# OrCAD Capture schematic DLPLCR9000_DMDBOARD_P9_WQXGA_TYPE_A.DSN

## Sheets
1 PAGE-01 Title Page
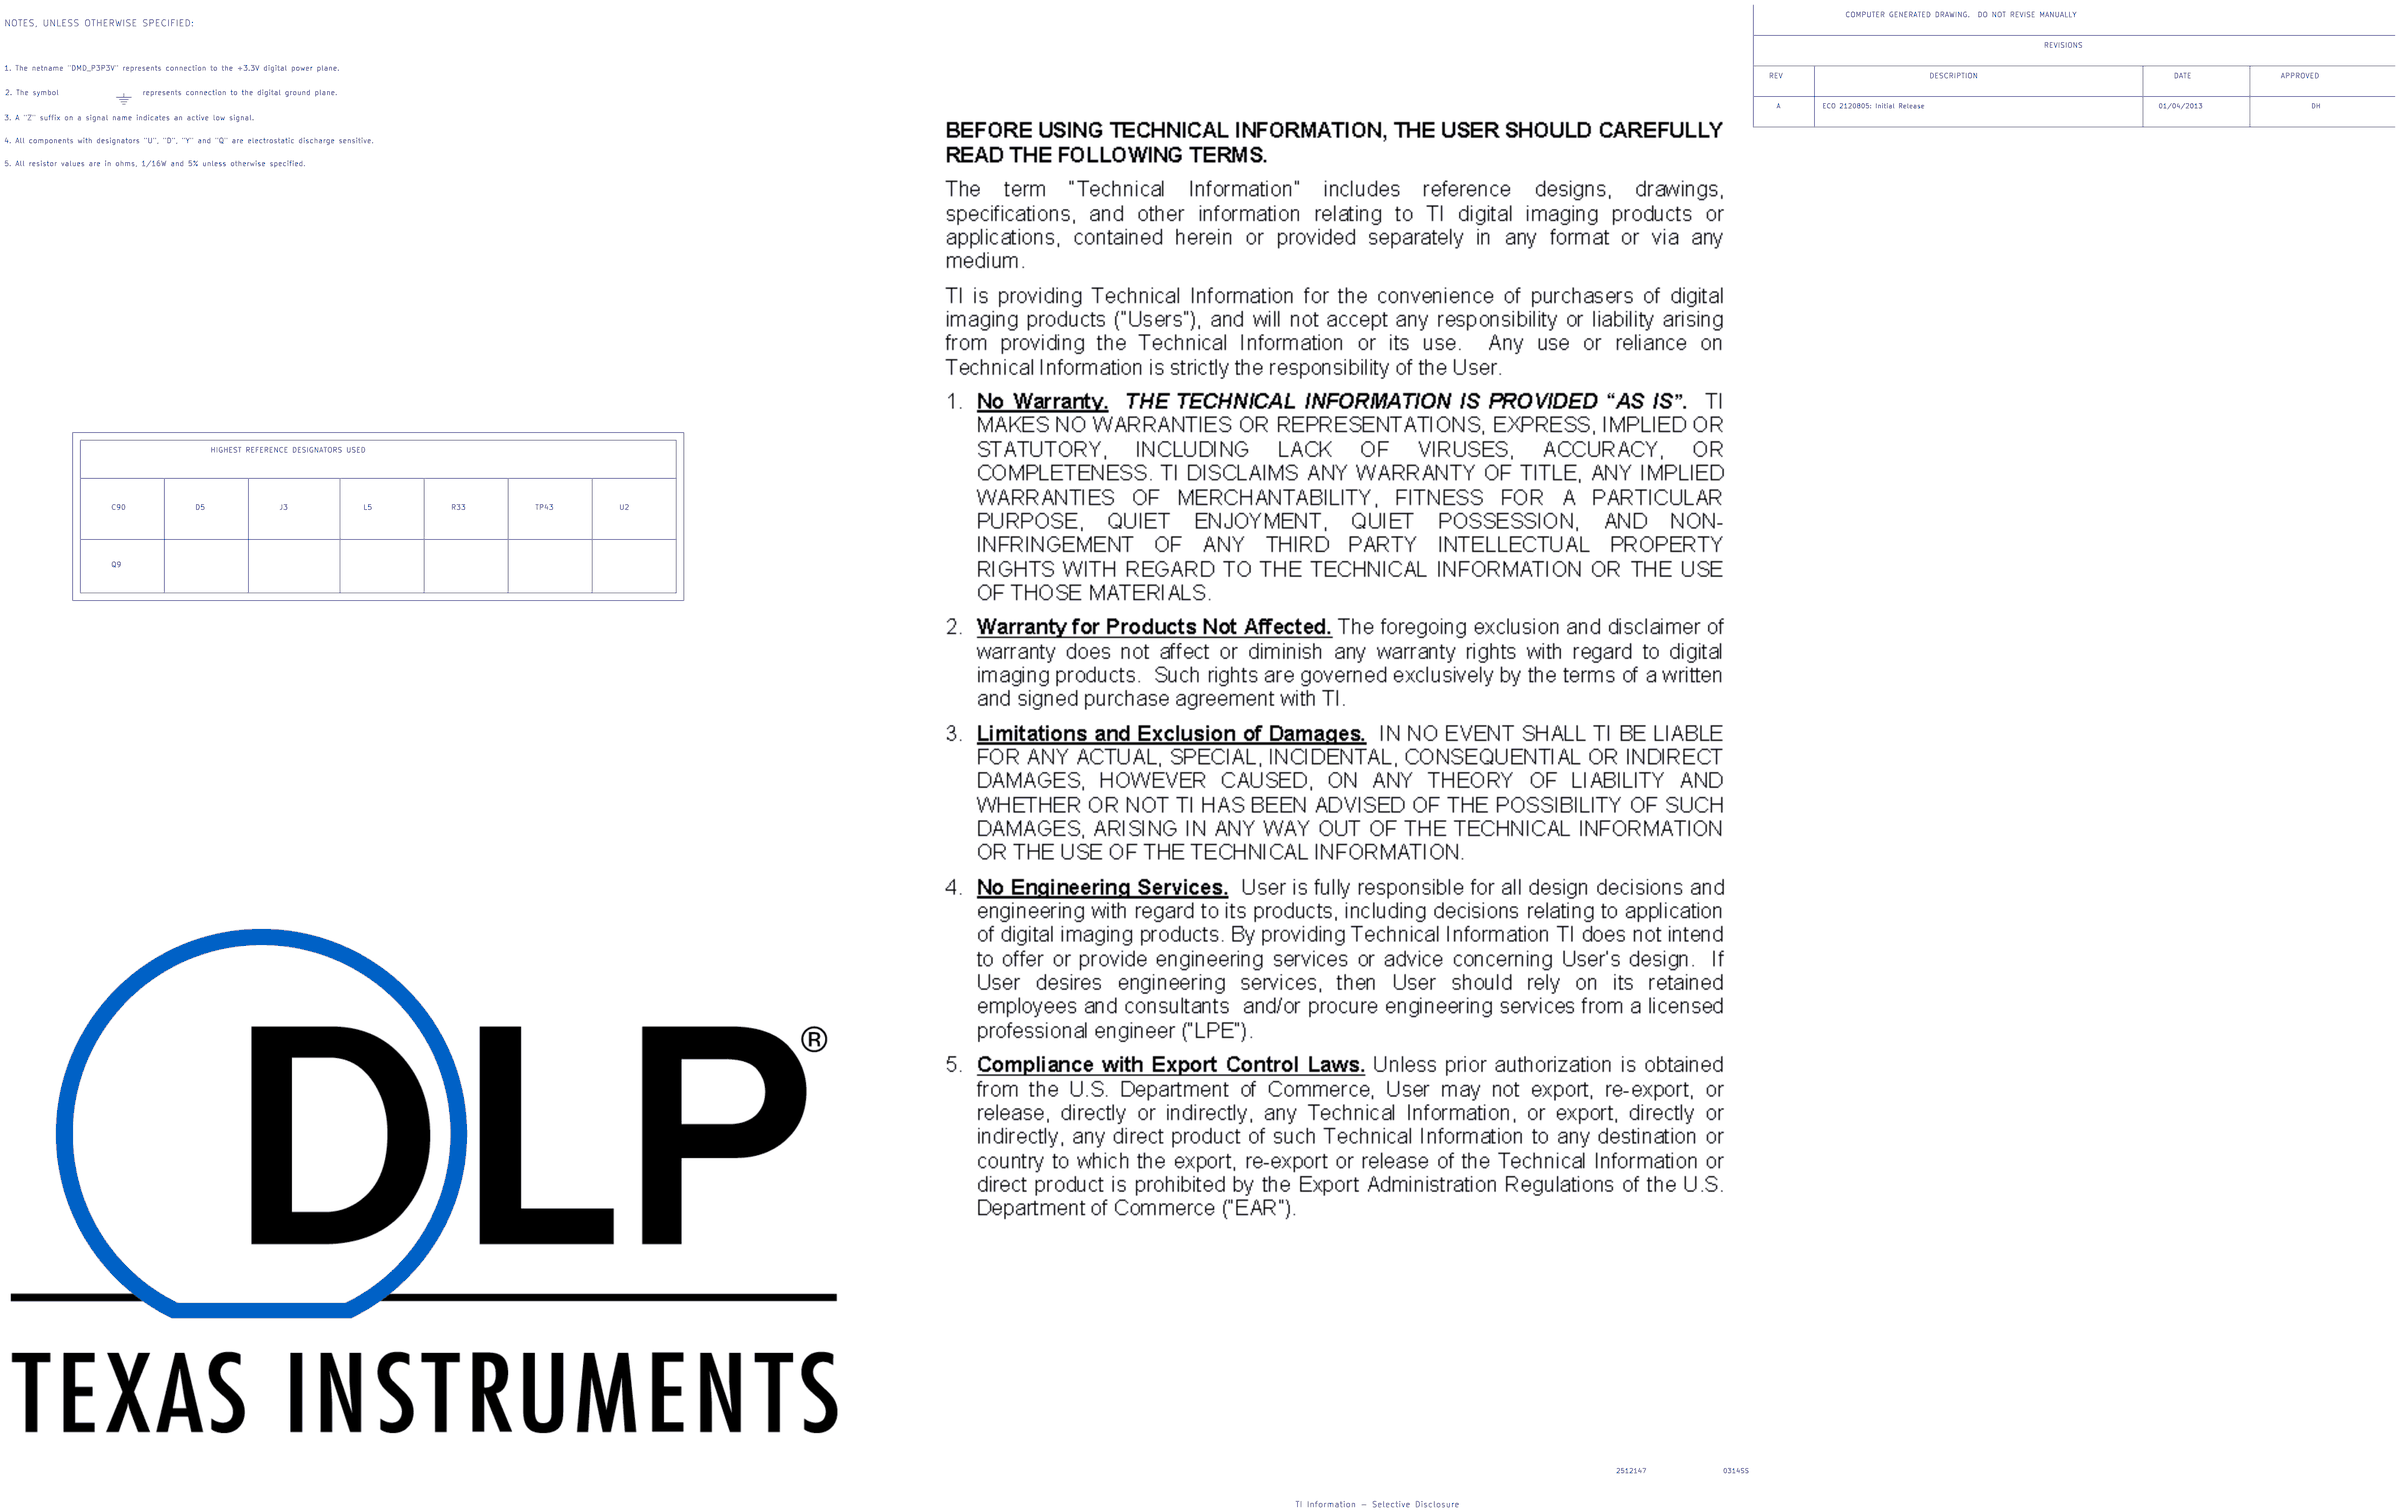
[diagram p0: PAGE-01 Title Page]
2 PAGE-02 Block Diagram
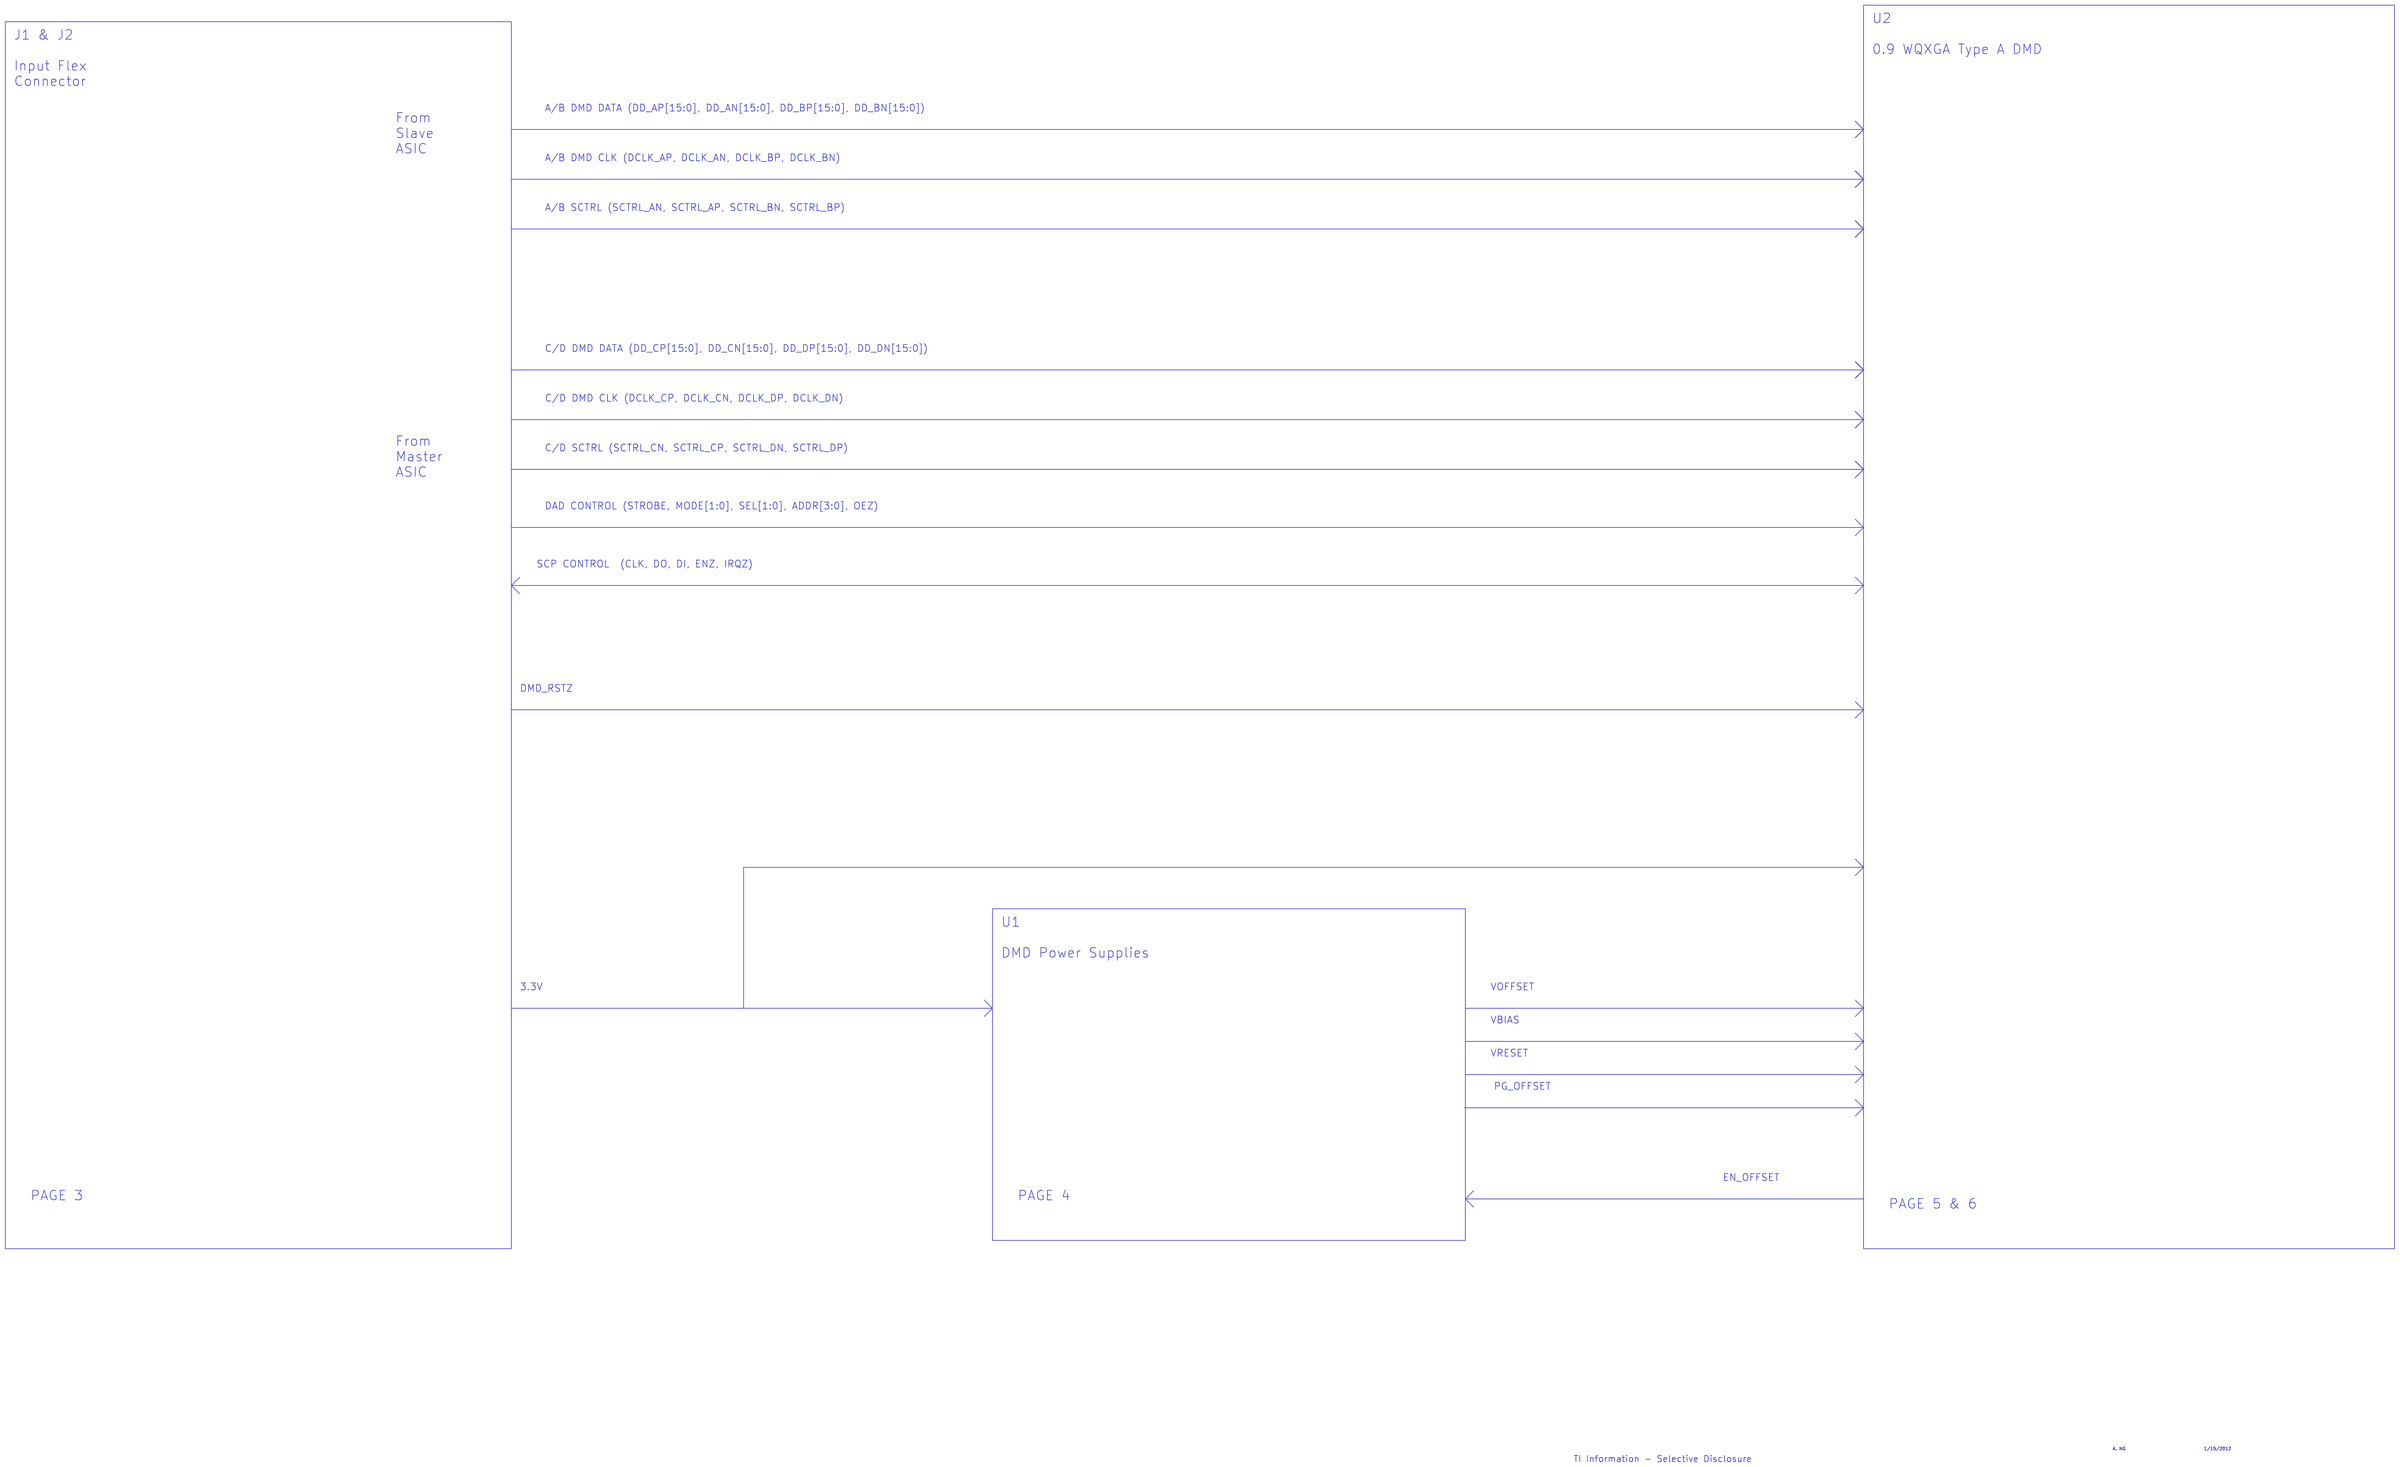
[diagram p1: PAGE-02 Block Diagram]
3 PAGE-03 Input Conn: size D
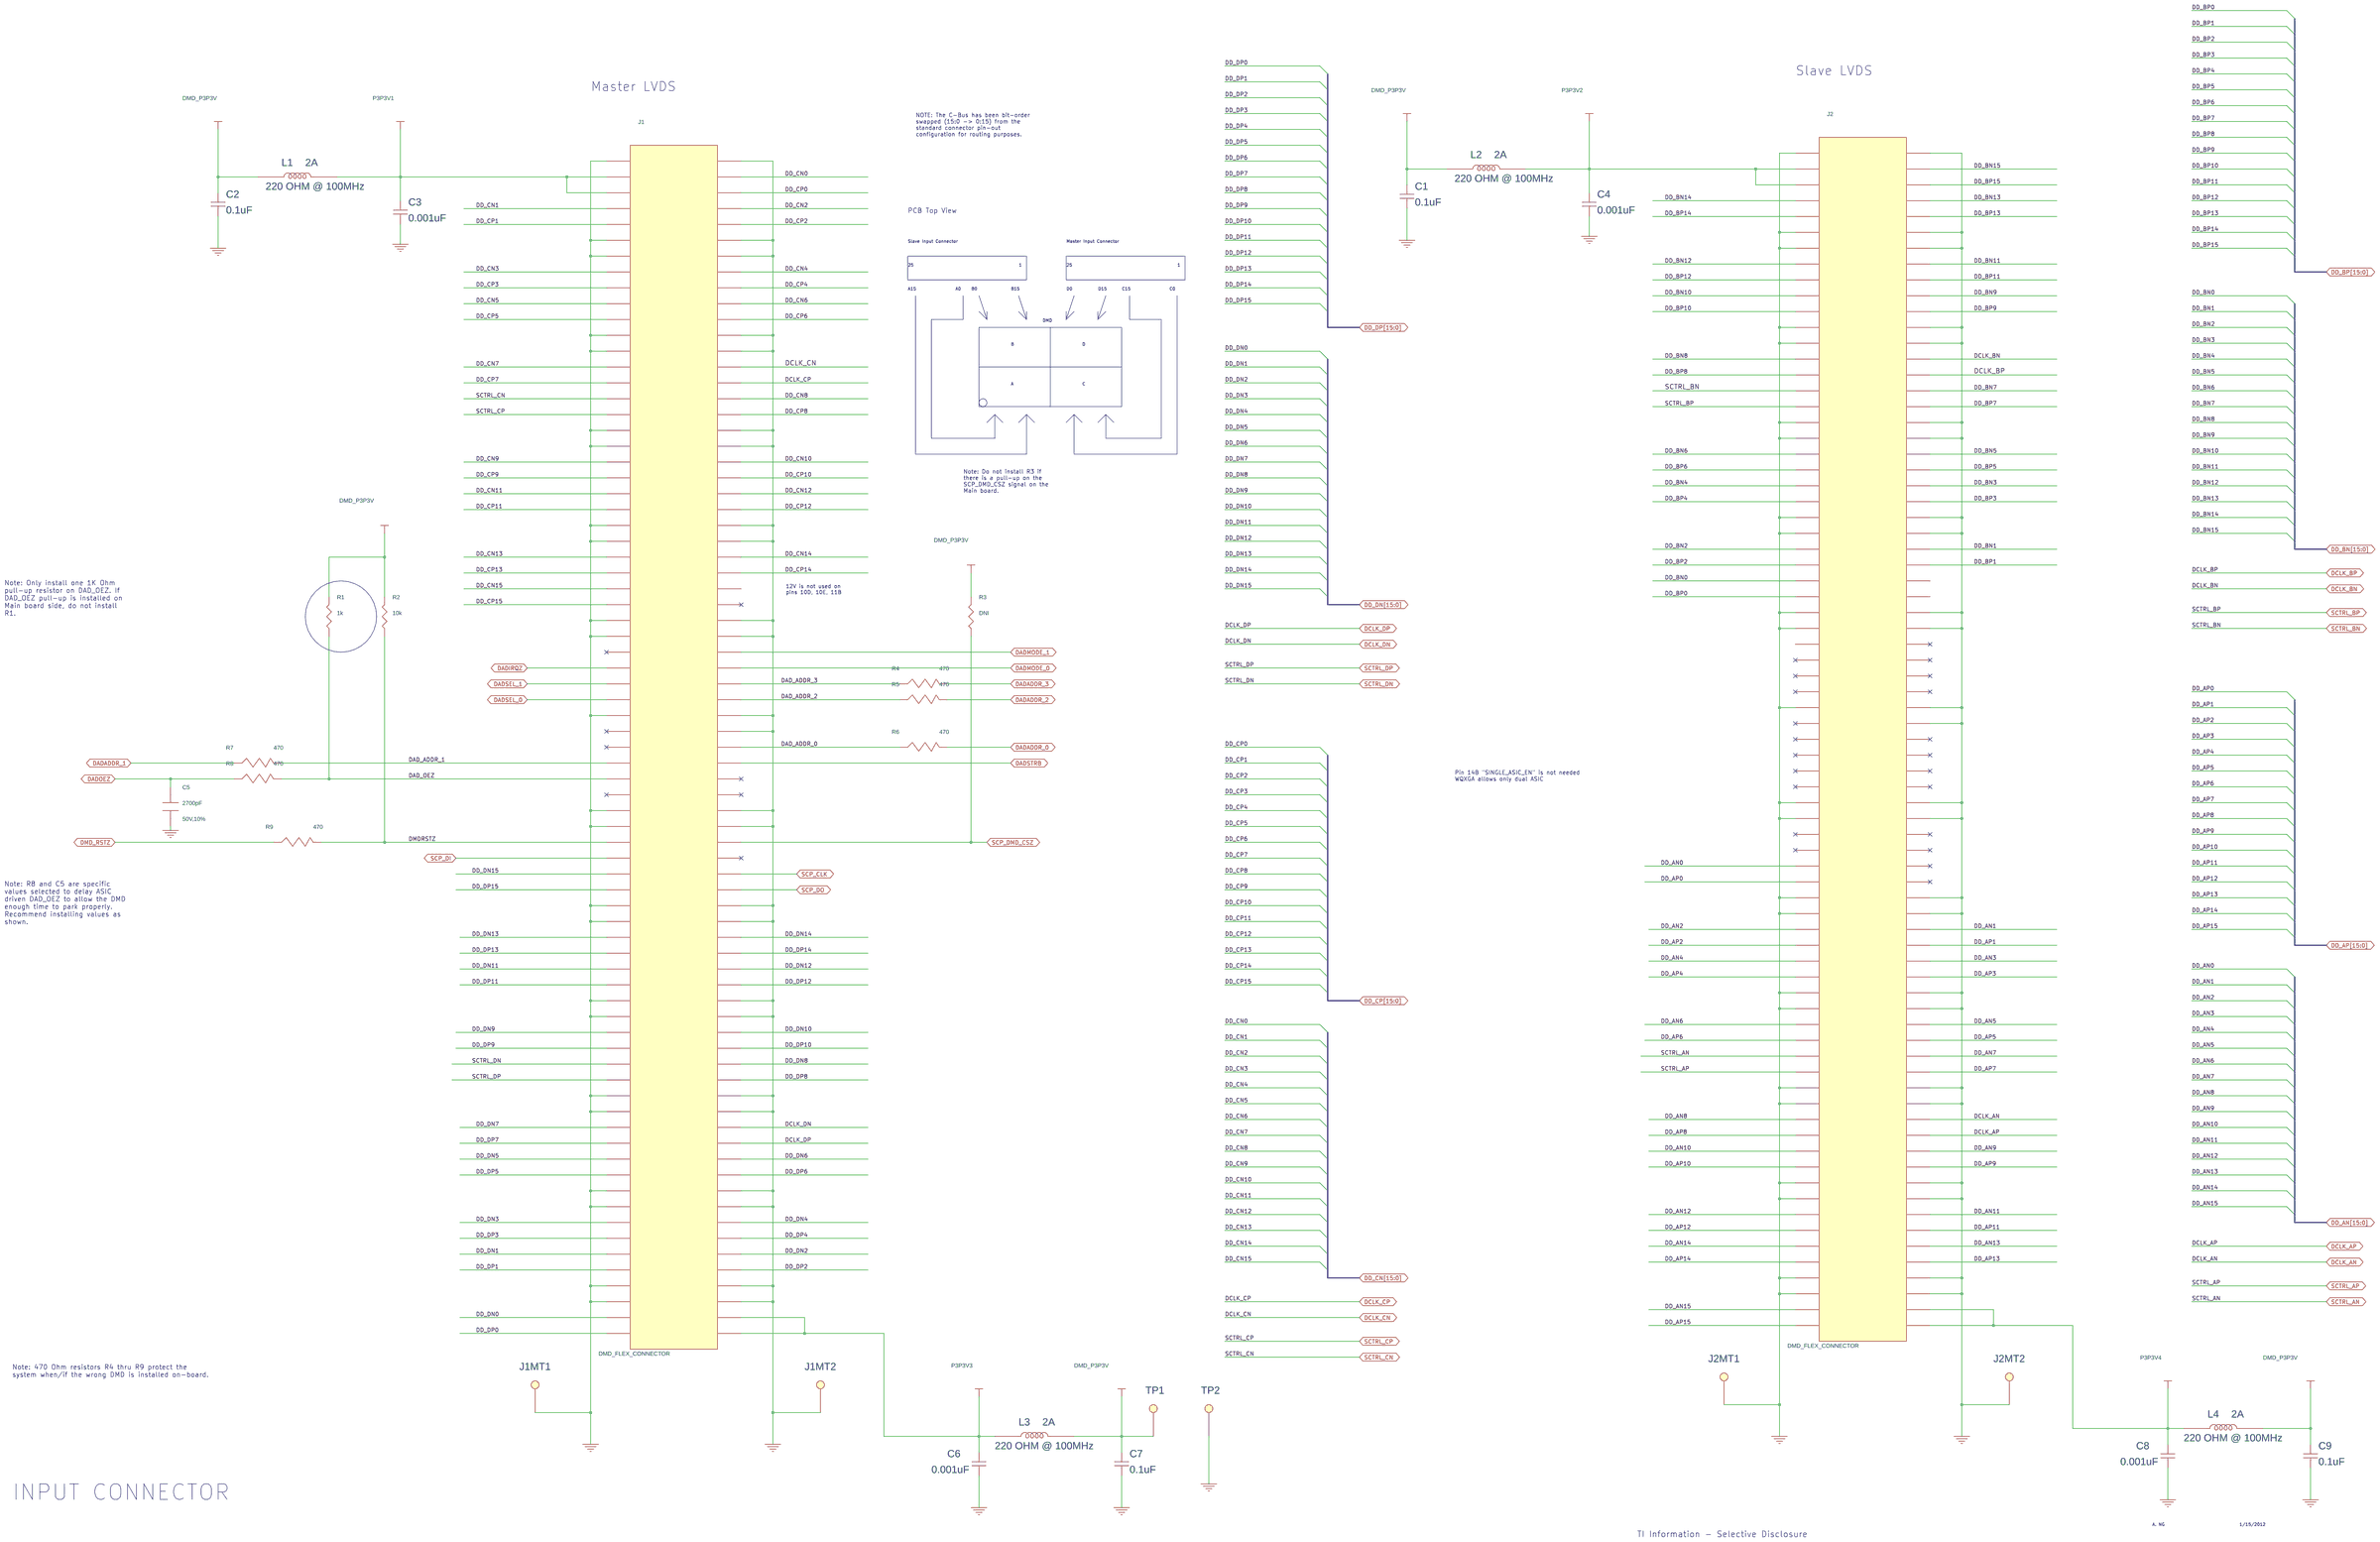
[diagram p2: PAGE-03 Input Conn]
4 PAGE-04 DMD Pwr Supplies: size D
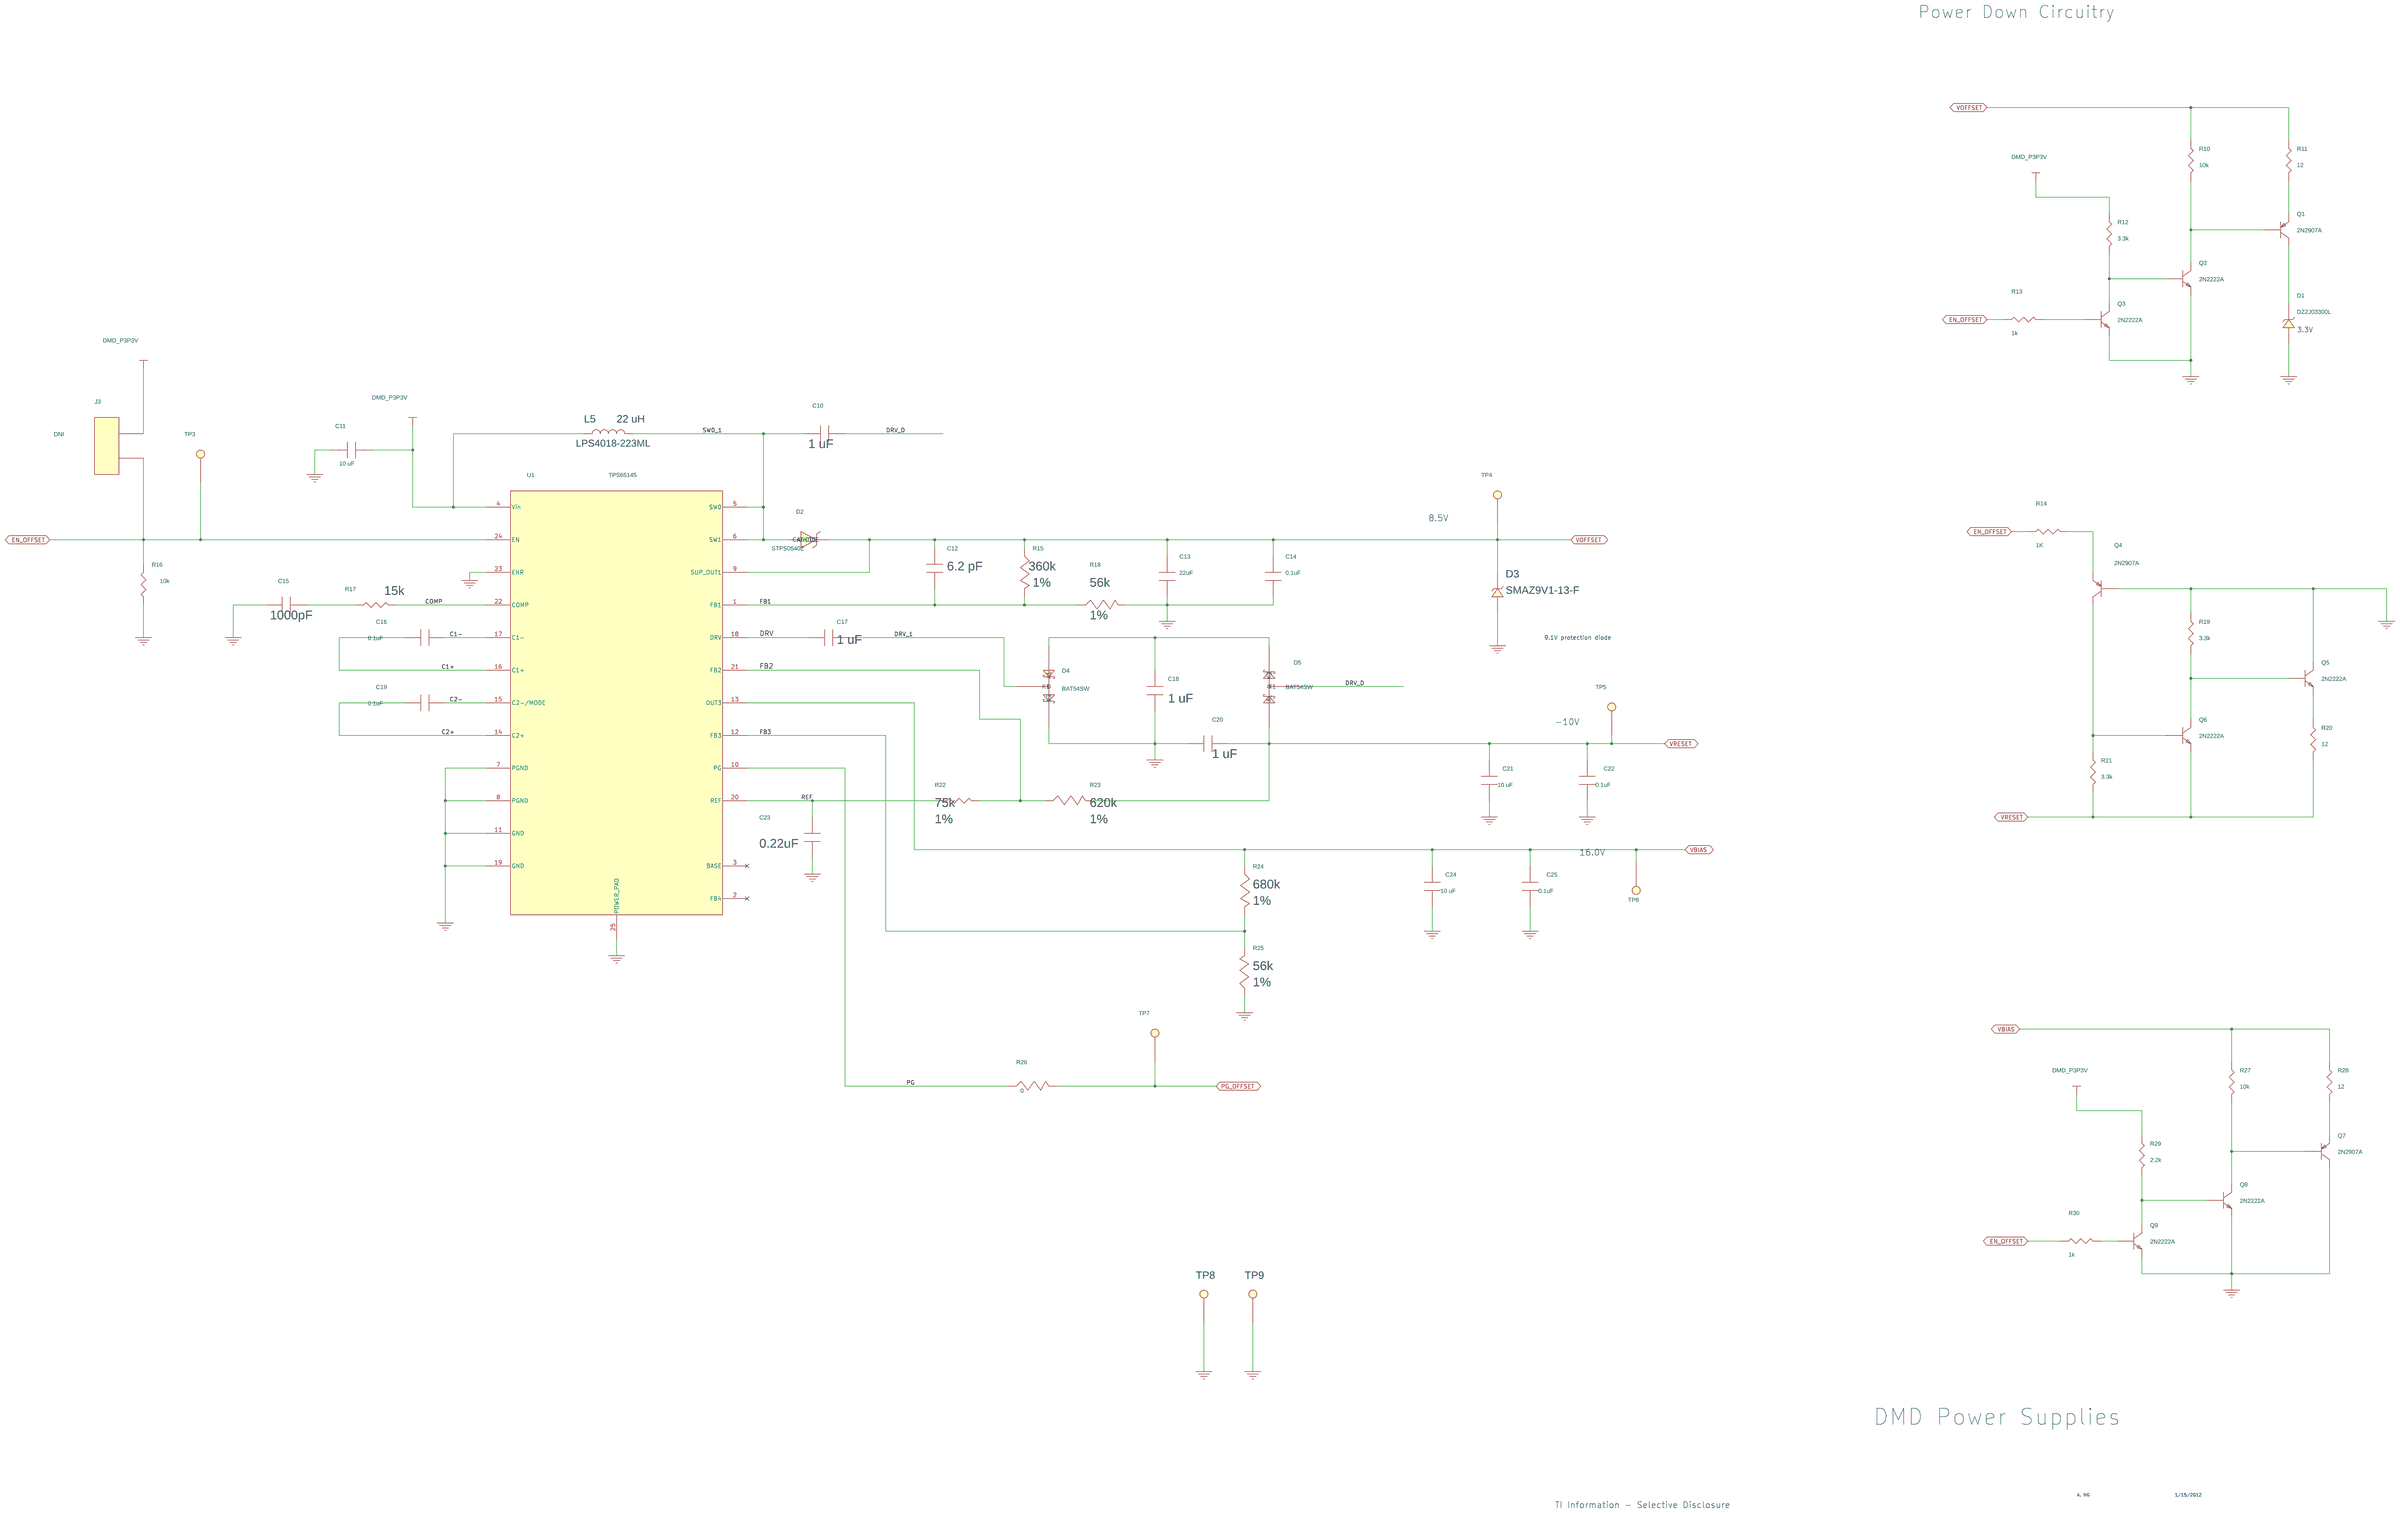
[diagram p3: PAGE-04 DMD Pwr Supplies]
5 PAGE-06 DMD Pwr/Gnd: size D
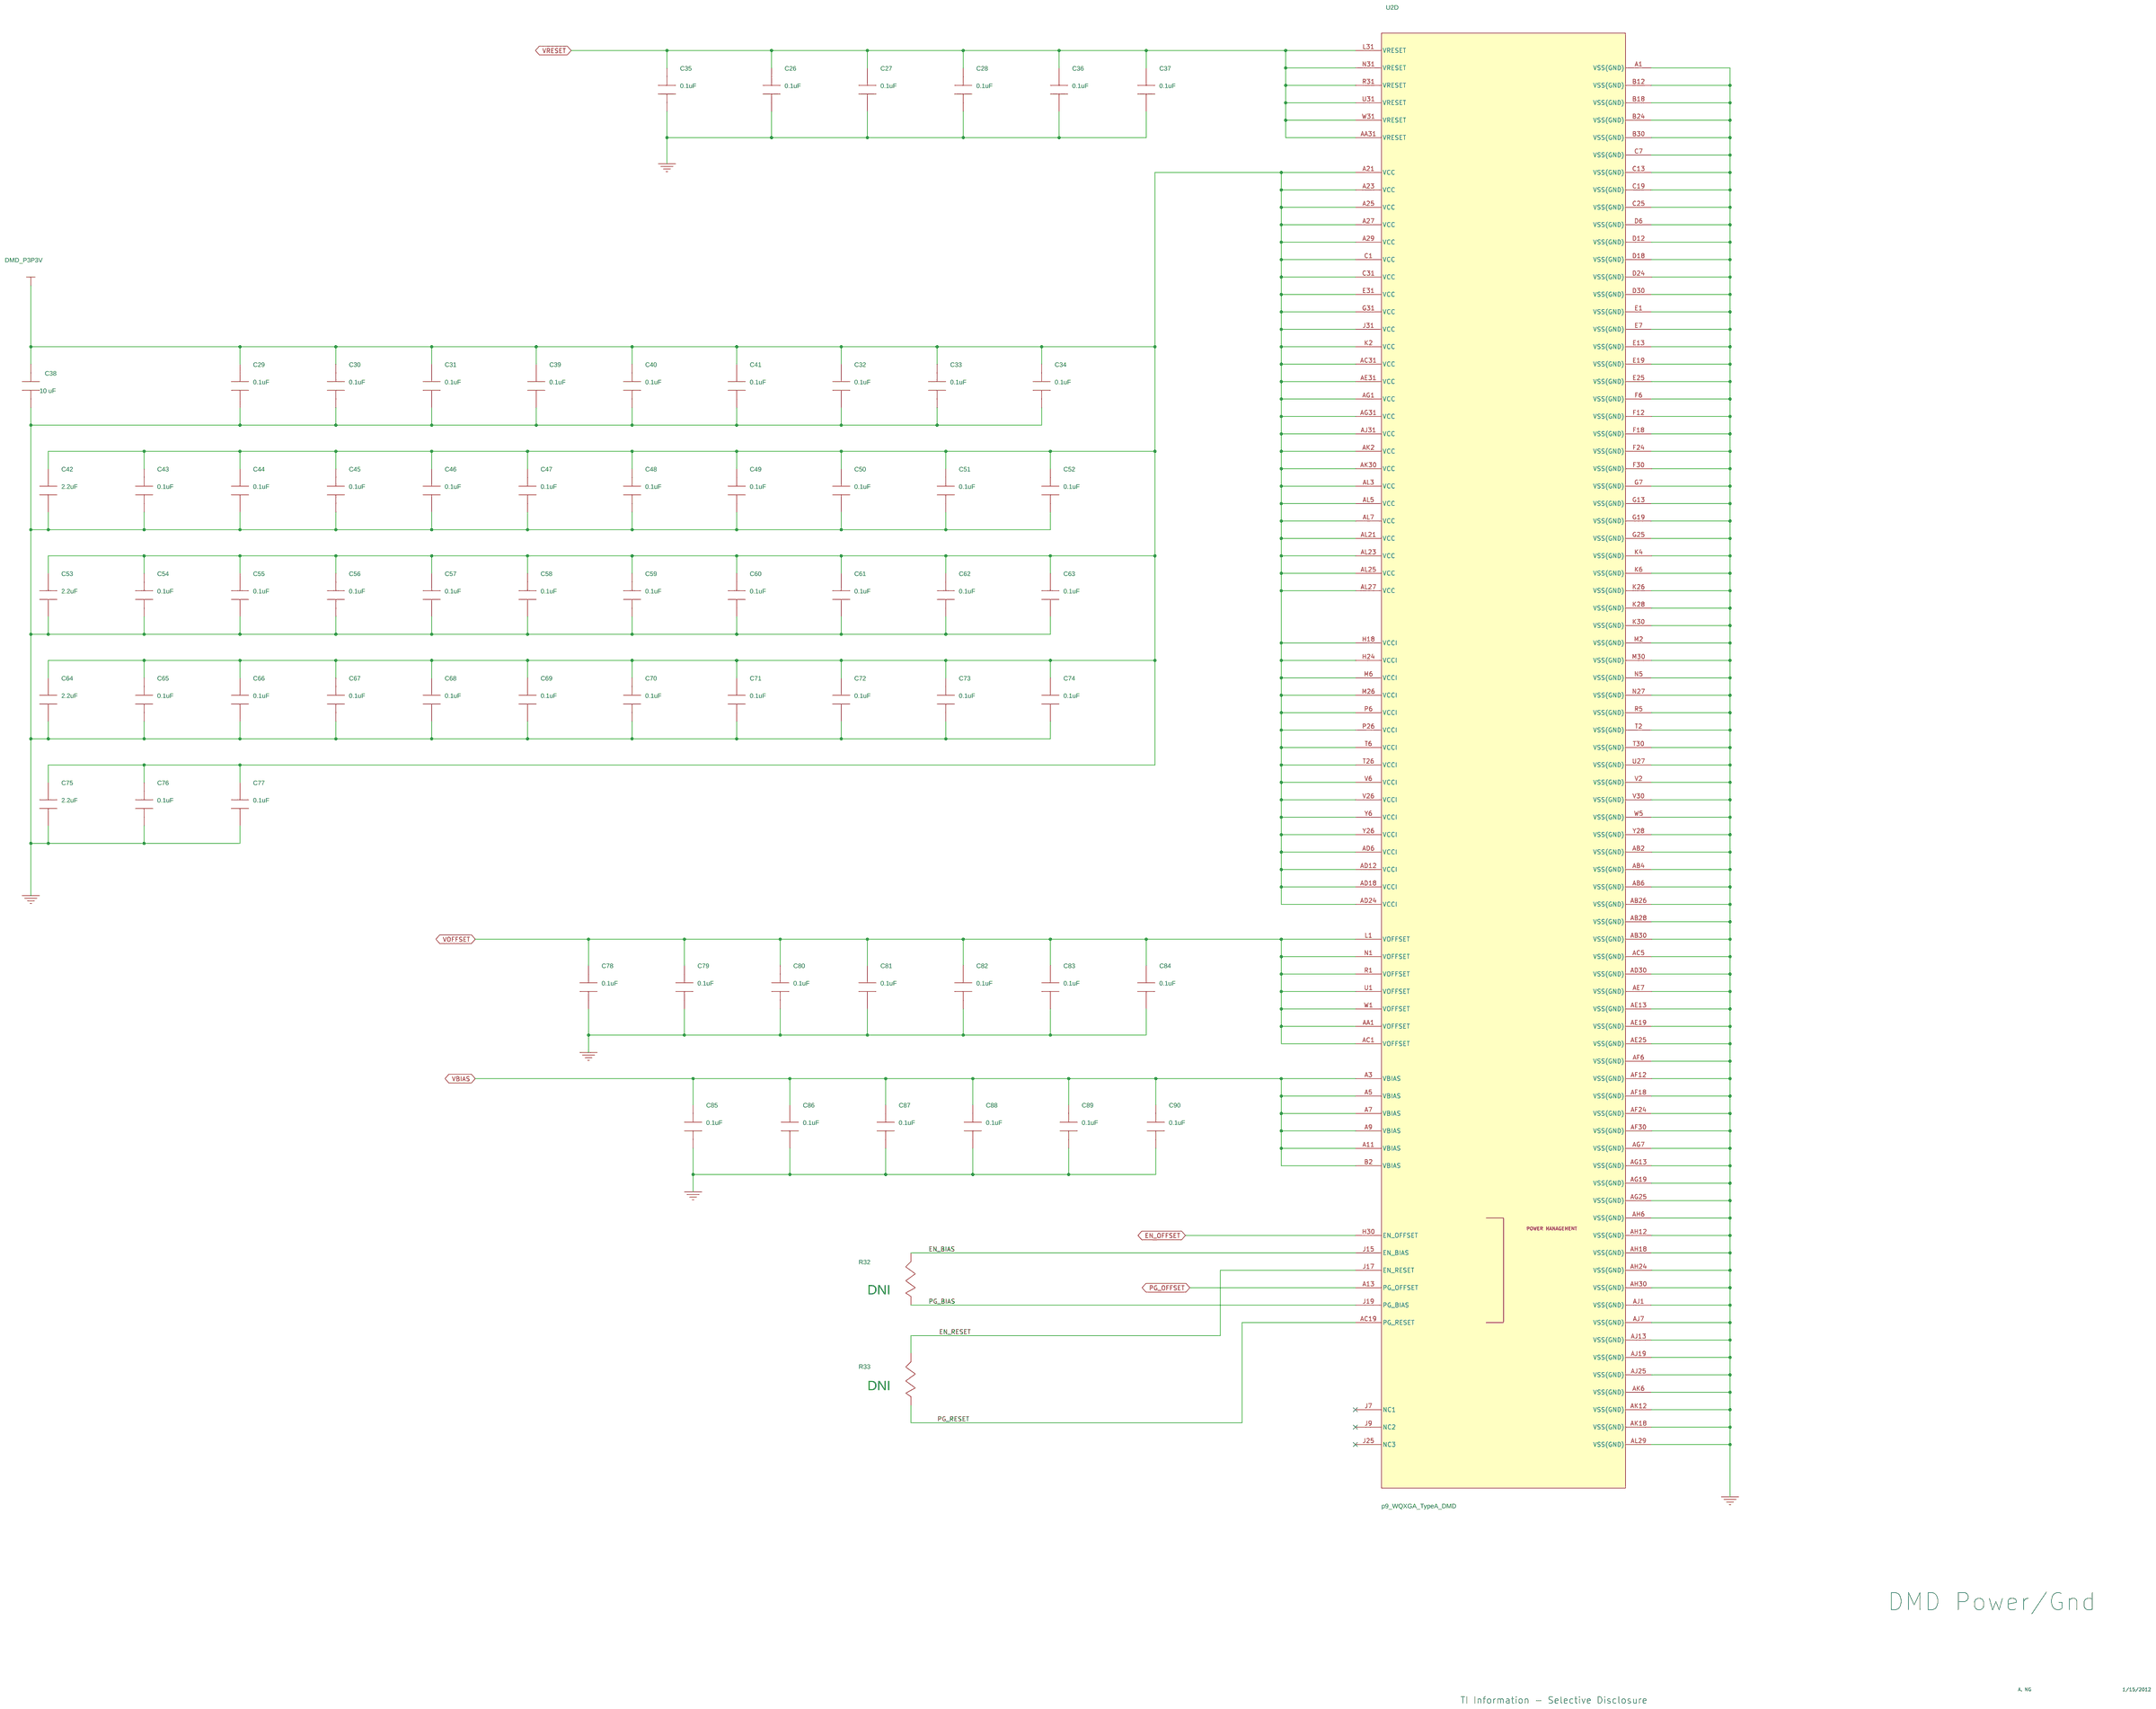
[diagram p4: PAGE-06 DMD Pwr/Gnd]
6 PAGE-05 DMD Data/Control: size D
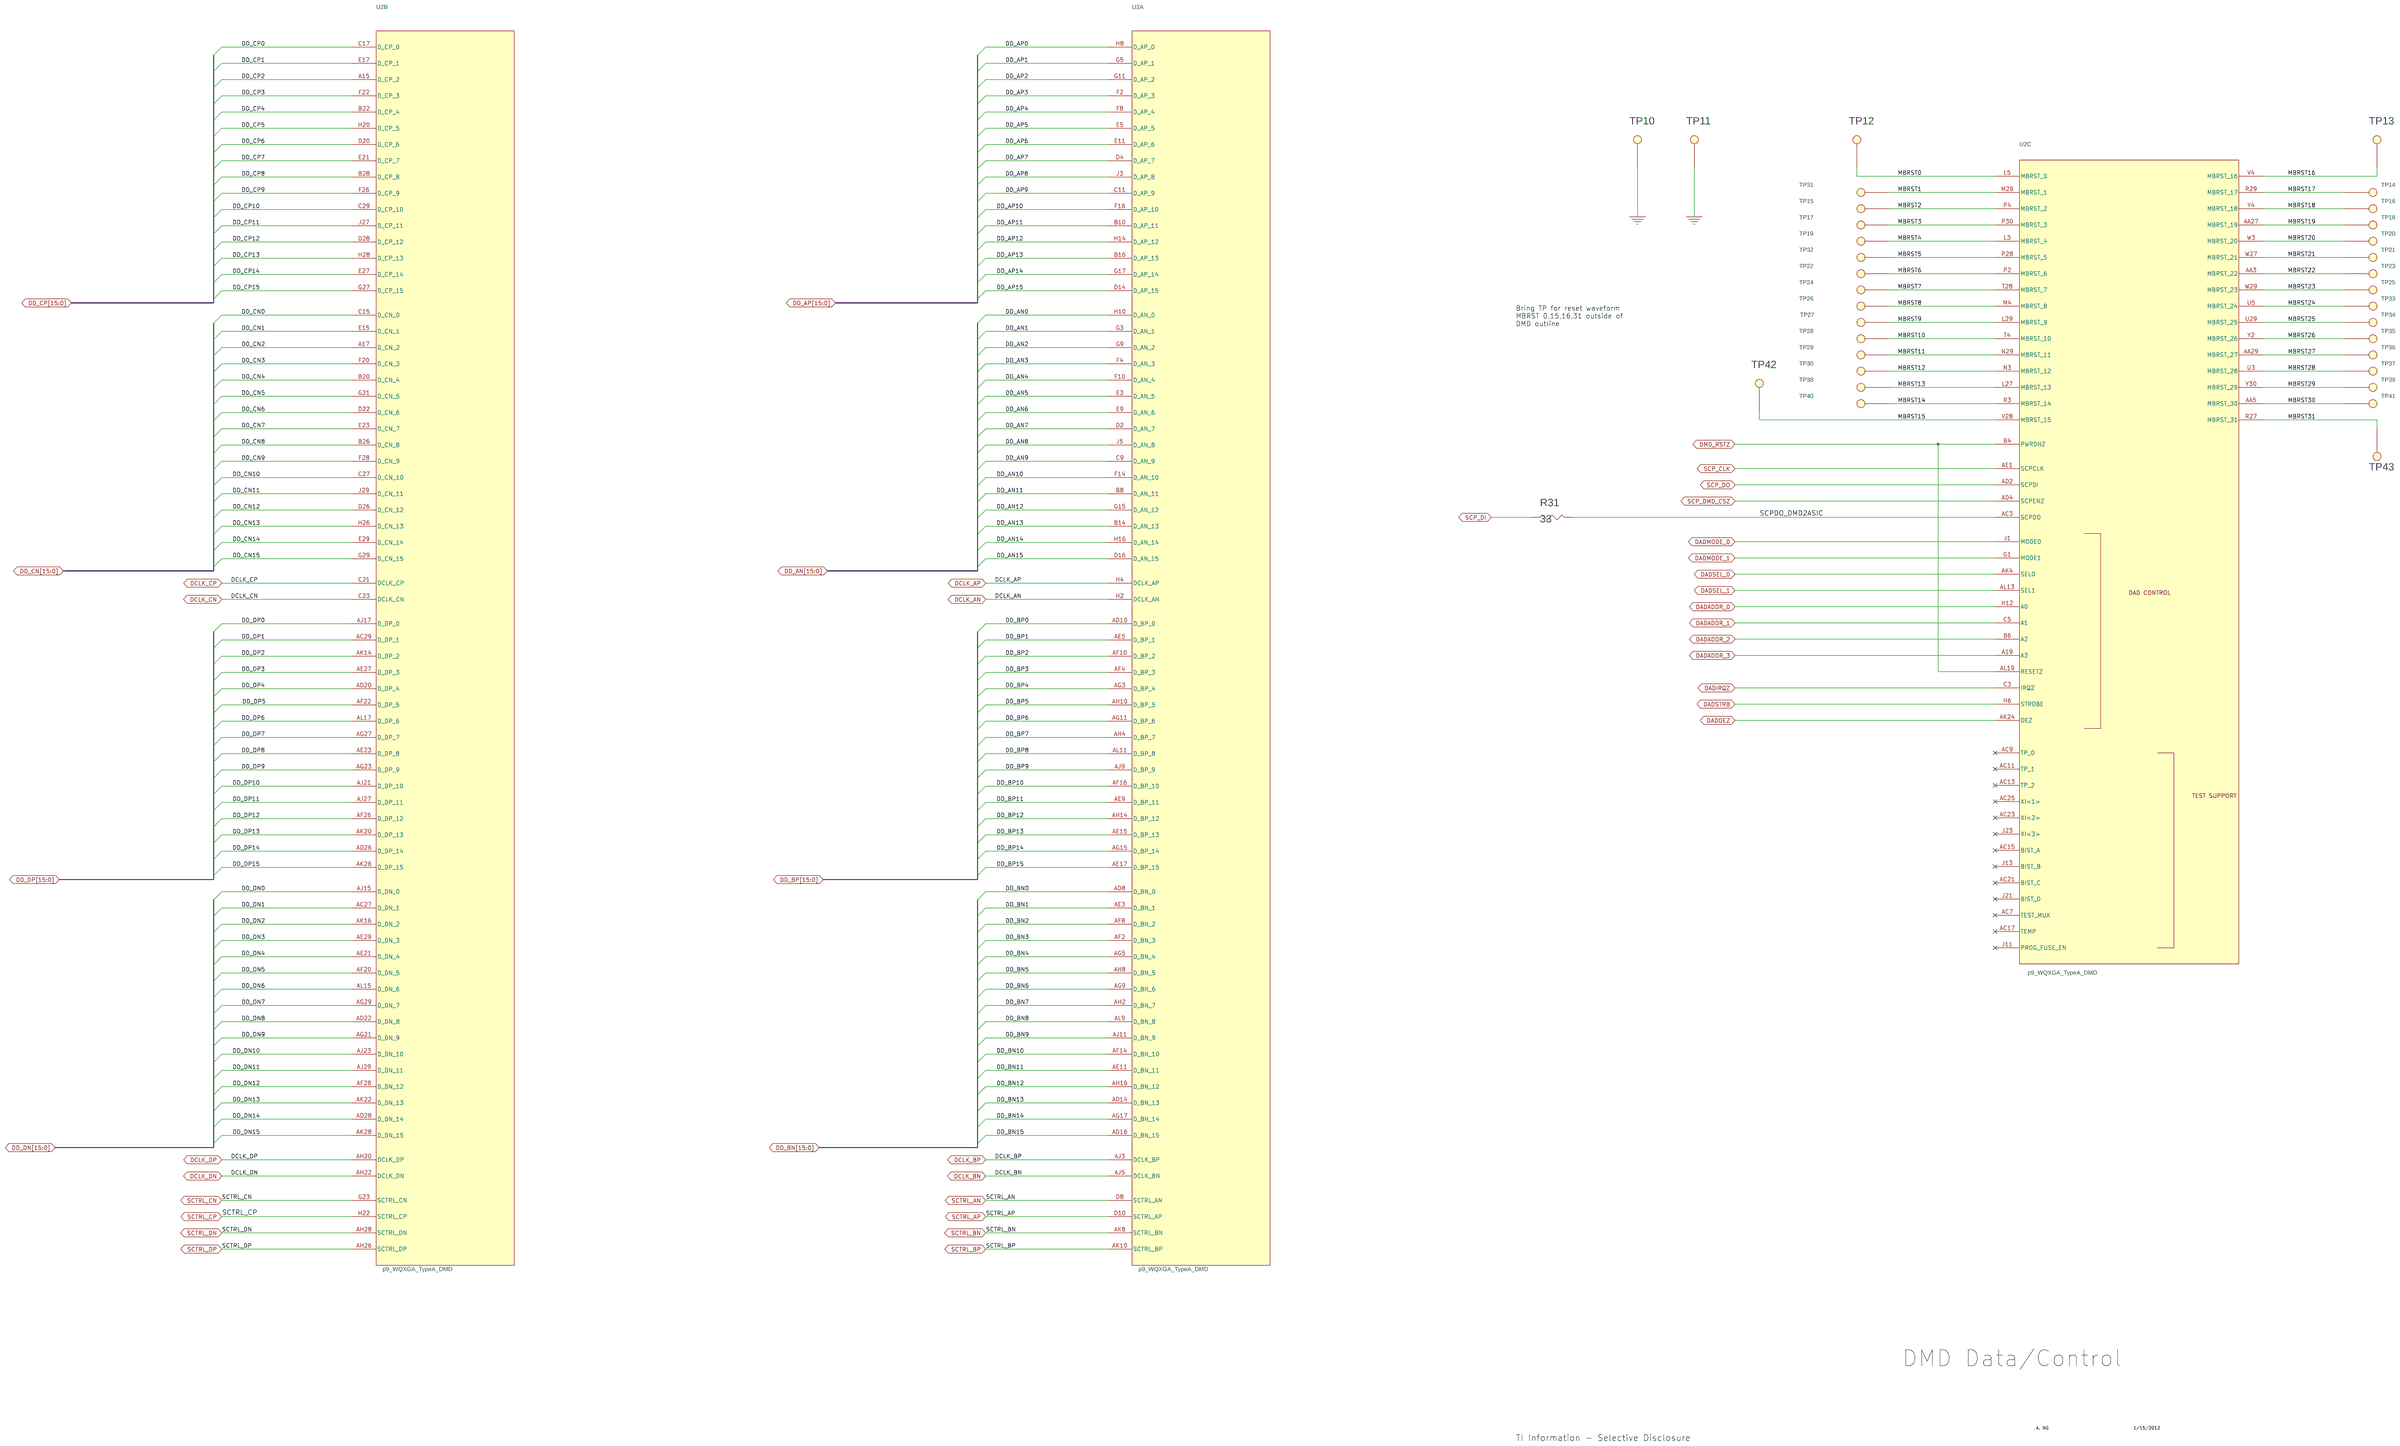
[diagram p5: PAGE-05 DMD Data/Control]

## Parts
sheet PAGE-03 Input Conn
C1  0.1uF  [0603AVX]
C2  0.1uF  [0603AVX]
C3  0.001uF  [0603AVX]
C4  0.001uF  [0603AVX]
C5  2700pF  [0402avx]
C6  0.001uF  [0603AVX]
C7  0.1uF  [0603AVX]
C8  0.001uF  [0603AVX]
C9  0.1uF  [0603AVX]
J1  DMD_FLEX_CONNECTOR  [CN150CUSTOM_REVB-MOD-NO-MH]
J1MT1  MT2  [MT2]
J1MT2  MT2  [MT2]
J2  DMD_FLEX_CONNECTOR  [CN150CUSTOM_REVB-MOD-NO-MH]
J2MT1  MT2  [MT2]
J2MT2  MT2  [MT2]
L1  220 OHM @ 100MHz  [0805avx]
L2  220 OHM @ 100MHz  [0805avx]
L3  220 OHM @ 100MHz  [0805avx]
L4  220 OHM @ 100MHz  [0805avx]
R1  1k  [0603AVX]
R2  10k  [0603AVX]
R3  DNI  [0603AVX]
R4  470  [0603avx]
R5  470  [0603avx]
R6  470  [0603avx]
R7  470  [0603avx]
R8  470  [0603avx]
R9  470  [0603avx]
TP1  Testpoint  [TP40_24]
TP2  Testpoint  [TP40_24]
sheet PAGE-04 DMD Pwr Supplies
C10  1 uF  [0603AVX]
C11  10 uF  [1210]
C12  6.2 pF  [0402AVX]
C13  22uF  [1210]
C14  0.1uF  [0805avx]
C15  1000pF  [0805avx]
C16  0.1uF  [0805avx]
C17  1 uF  [0603AVX]
C18  1 uF  [0603AVX]
C19  0.1uF  [0805avx]
C20  1 uF  [0603AVX]
C21  10 uF  [1210]
C22  0.1uF  [0805avx]
C23  0.22uF  [0805AVX]
C24  10 uF  [1210]
C25  0.1uF  [0805avx]
D1  DZ2J03300L  [DIO_SMINI2F1_PAN]
D2  STPS0540Z  [SOD123]
D3  9.1V  [DO-214AC]
D4  BAT54SW  [sot323avx]
D5  BAT54SW  [sot323avx]
J3  DNI  [CONN_2POS_2p54MM]
L5  22 uH  [IND_LPS4018]
Q1  2N2907A  [SOT23-3_FC]
Q2  2N2222A  [SOT23-3_FC]
Q3  2N2222A  [SOT23-3_FC]
Q4  2N2907A  [SOT23-3_FC]
Q5  2N2222A  [SOT23-3_FC]
Q6  2N2222A  [SOT23-3_FC]
Q7  2N2907A  [SOT23-3_FC]
Q8  2N2222A  [SOT23-3_FC]
Q9  2N2222A  [SOT23-3_FC]
R10  10k  [0402]
R11  12  [0603]
R12  3.3k  [0402]
R13  1k  [0402]
R14  1K  [0402]
R15  360k  [0603avx]
R16  10k  [0603AVX]
R17  15k  [0603AVX]
R18  56k  [0603avx]
R19  3.3k  [0402]
R20  12  [0603]
R21  3.3k  [0402]
R22  75k  [0603avx]
R23  620k  [0603avx]
R24  680k  [0603avx]
R25  56k  [0603avx]
R26  0  [0603avx]
R27  10k  [0402]
R28  12  [0603]
R29  2.2k  [0402]
R30  1k  [0402]
TP3  Testpoint  [tp40_24]
TP4  Testpoint  [tp40_24]
TP5  Testpoint  [tp40_24]
TP6  Testpoint  [tp40_24]
TP7  Testpoint  [tp40_24]
TP8  Testpoint  [TP40_24]
TP9  Testpoint  [TP40_24]
U1  TPS65145  [SOIC24-PWP_TI]
sheet PAGE-05 DMD Data/Control
R31  33  [0603AVX]
TP10  Testpoint  [TP40_24]
TP11  Testpoint  [TP40_24]
TP12  Testpoint  [TP40_24]
TP13  Testpoint  [TP40_24]
TP14  Testpoint  [tp-40RD]
TP15  Testpoint  [tp-40RD]
TP16  Testpoint  [tp-40RD]
TP17  Testpoint  [tp-40RD]
TP18  Testpoint  [tp-40RD]
TP19  Testpoint  [tp-40RD]
TP20  Testpoint  [tp-40RD]
TP21  Testpoint  [tp-40RD]
TP22  Testpoint  [tp-40RD]
TP23  Testpoint  [tp-40RD]
TP24  Testpoint  [tp-40RD]
TP25  Testpoint  [tp-40RD]
TP26  Testpoint  [tp-40RD]
TP27  Testpoint  [tp-40RD]
TP28  Testpoint  [tp-40RD]
TP29  Testpoint  [tp-40RD]
TP30  Testpoint  [tp-40RD]
TP31  Testpoint  [tp-40RD]
TP32  Testpoint  [tp-40RD]
TP33  Testpoint  [tp-40RD]
TP34  Testpoint  [tp-40RD]
TP35  Testpoint  [tp-40RD]
TP36  Testpoint  [tp-40RD]
TP37  Testpoint  [tp-40RD]
TP38  Testpoint  [tp-40RD]
TP39  Testpoint  [tp-40RD]
TP40  Testpoint  [tp-40RD]
TP41  Testpoint  [tp-40RD]
TP42  Testpoint  [TP40_24]
TP43  Testpoint  [TP40_24]
U2  p9_WQXGA_TypeA_DMD  [DMD_085XHD1440]  (sections A,B,C,D)
sheet PAGE-06 DMD Pwr/Gnd
C26  0.1uF  [0603avx]
C27  0.1uF  [0603avx]
C28  0.1uF  [0603avx]
C29  0.1uF  [0603avx]
C30  0.1uF  [0603avx]
C31  0.1uF  [0603avx]
C32  0.1uF  [0603avx]
C33  0.1uF  [0603avx]
C34  0.1uF  [0603avx]
C35  0.1uF  [0603avx]
C36  0.1uF  [0603avx]
C37  0.1uF  [0603avx]
C38  10 uF  [1210]
C39  0.1uF  [0603avx]
C40  0.1uF  [0603avx]
C41  0.1uF  [0603avx]
C42  2.2uF  [0603avx]
C43  0.1uF  [0603avx]
C44  0.1uF  [0603avx]
C45  0.1uF  [0603avx]
C46  0.1uF  [0603avx]
C47  0.1uF  [0603avx]
C48  0.1uF  [0603avx]
C49  0.1uF  [0603avx]
C50  0.1uF  [0603avx]
C51  0.1uF  [0603avx]
C52  0.1uF  [0603avx]
C53  2.2uF  [0603avx]
C54  0.1uF  [0603avx]
C55  0.1uF  [0603avx]
C56  0.1uF  [0603avx]
C57  0.1uF  [0603avx]
C58  0.1uF  [0603avx]
C59  0.1uF  [0603avx]
C60  0.1uF  [0603avx]
C61  0.1uF  [0603avx]
C62  0.1uF  [0603avx]
C63  0.1uF  [0603avx]
C64  2.2uF  [0603avx]
C65  0.1uF  [0603avx]
C66  0.1uF  [0603avx]
C67  0.1uF  [0603avx]
C68  0.1uF  [0603avx]
C69  0.1uF  [0603avx]
C70  0.1uF  [0603avx]
C71  0.1uF  [0603avx]
C72  0.1uF  [0603avx]
C73  0.1uF  [0603avx]
C74  0.1uF  [0603avx]
C75  2.2uF  [0603avx]
C76  0.1uF  [0603avx]
C77  0.1uF  [0603avx]
C78  0.1uF  [0603avx]
C79  0.1uF  [0603avx]
C80  0.1uF  [0603avx]
C81  0.1uF  [0603avx]
C82  0.1uF  [0603avx]
C83  0.1uF  [0603avx]
C84  0.1uF  [0603avx]
C85  0.1uF  [0603avx]
C86  0.1uF  [0603avx]
C87  0.1uF  [0603avx]
C88  0.1uF  [0603avx]
C89  0.1uF  [0603avx]
C90  0.1uF  [0603avx]
R32  DNI  [0603avx]
R33  DNI  [0603avx]

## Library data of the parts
C1 C2 C7 C9 = CAP_NP: Capacitor; CCA ITEM: 1; MFG: AVX; Part Number: 0603YC104KAT2A; Rating: 16V; Tolerance: 10%; Type: X7R
C3 C4 C6 C8 = CAP_NP: Capacitor; CCA ITEM: 3; MFG: AVX; Part Number: 06035C102KAT2A; Rating: 50V; Tolerance: 10%; Type: X7R
C5 = CAP_NP_dsize: Capacitor; ESR: <ESR>; ICA_MFR_NAME: PANASONIC; ICA_PARTNUM: $$2075017$$ECJ1VB1E104K; MFG: Yageo; Part Number: CC0402KRX7R9BB272; Rating: 50V; Rating/Tolerance: 50V,10%; Tolerance: 10%; Type: X7R
J1 J2 = cSTACK_FLEX_CONN_2: Connector; MFG: INTERCON SYSTEMS; Part Number: CN150CUSTOM_REVB
J1MT1 J1MT2 J2MT1 J2MT2 TP1 TP2 TP8-TP13 TP42 TP43 = Testpoint: Test point
L1-L4 = FERRITE_L: Ferrite; CCA ITEM: 59; CURRENT: 2A; ICA_MFR_NAME: MURATA; ICA_PARTNUM: $$1507311$$BLM21PG221SG; MFG: MURATA; Part Number: BLM21PG221SN1D; Rating: 2A, 50mOhm; Tolerance: 25%
R1 = R: Resistor; CCA ITEM: ?; Do Not Install: Do Not Install; MFG: Panasonic; Part Number: ERJ-3GEYJ102V; Rating: 1/10W; Tolerance: 5%
R2 R16 = R: Resistor; CCA ITEM: ?; MFG: Panasonic; Part Number: ERJ-3GEYJ103V; Rating: 1/10W; Tolerance: 5%
R3 = R: Resistor; CCA ITEM: ?; Do Not Install: Do Not Install; MFG: Panasonic; Part Number: ERJ-3GEYJ103V; Rating: 1/10W; Tolerance: 5%
R4-R9 = RESISTOR_dsize: Resistor; CCA ITEM: 110; ICA_MFR_NAME: PANASONIC; ICA_PARTNUM: $$1785380$$ERJ-3GSYJ330V; MFG: Panasonic; Part Number: ERJ-3GEYJ471; RATING/TOLERANCE: <RATING/TOLERANCE>; Rating: 1/10W; Tolerance: 5%
C10 C17 C18 C20 = CAP_NP_dsize: Capacitor; Mfg: AVX; Part Number: 06033D105KAT2A; Rating: 25V; Tolerance: 10%; Type: X5R
C11 C21 C24 C38 = CAP_NP_dsize: Capacitor; ESR: <ESR>; Mfg: Murata; Part Number: GRM32DR61E106KA12L; Rating: 25V; Rating/Tolerance: 25V,10%; Tolerance: 10%; Type: X5R
C12 = CAP_NP_dsize: Capacitor; Mfg: Murata; Part Number: GJM1555C1H6R2CB01D; Rating: 50V; Type: NP0
C13 = CAP_NP_dsize: Capacitor; ESR: <ESR>; Mfg: Taiyo Yuden; Rating: 16V; Rating/Tolerance: 16V,20%; Tolerance: 20%; Type: X5R; part number: EMK325BJ226MM-T
C14 C22 C25 = CAP_NP_dsize: Cap; ESR: 0.1 OHM; ICA_MFR_NAME: NIC; ICA_PARTNUM: $$2075017$$NMC1206X7R104K50; Mfg: AVX; Part Number: 08055C104MAT2A; Rating: 50V; Rating/Tolerance: 50V, 20%; Tolerance: 20%; Type: X7R
C15 = CAP_NP_dsize: Capacitor; Mfg: Panasonic; Part Number: ECJ-2VB1H102K; Rating: 50V; Tolerance: 10%; Type: X7R
C16 C19 = CAP_NP_dsize: Capacitor; ESR: 0.1 OHM; ICA_MFR_NAME: NIC; ICA_PARTNUM: $$2075017$$NMC1206X7R104K50; Mfg: AVX; Part Number: 08055C104MAT2A; Rating: 50V; Rating/Tolerance: 50V; Tolerance: 20%; Type: X7R
C23 = CAP_NP_dsize: Capacitor; Mfg: TDK; Part Number: C2012X8R1E224K; Rating: 25V; Tolerance: 10%; Type: X8R
D1 = DIODE_ZENER: Diode Zener; Mfg: Panasonic; Rating: 3.3V 200mW
D2 = DIODE_SCHOTTKY_dsize: Diode Schottky; Mfg: STM; Rating: 40V 0.5A
D3 = DIODE_ZENER: DIODE ZENER 9.1V 1W SMA; CCA ITEM: 9; MFG: DIODES INC; Part Number: SMAZ9V1-13-F; RATING: 1W; RATING/TOLERANCE: 5%; Tolerance: 5%
D4 D5 = BAT54SW: Diode Schottky; ICA_MFR_NAME: PHILIPS SEMICONDUCTOR; ICA_PARTNUM: $$1491280$$BAT54SW; Mfg: NXP; Rating: 30V
J3 = CONN_HEADER_2POS_.100_SNGL_SMD: Do Not Install: Do Not Install; Mfg: Samtec; Part Number: TSM-102-01-T-SV
L5 = INDUCTOR: Inductor; CCA ITEM: 12; ICA_MFR_NAME: STEWARD; ICA_PARTNUM: $$731362$$MI0603J680R-10; MFG: COILCRAFT; Part Number: LPS4018-223ML; RATING: 0.65 A, 0.36Ohm; TOLERANCE: 20%
Q1 Q4 Q7 = 2N2907A: Transistor PNP; Mfg: Fairchild; Part Number: MMBT2907A; Rating: 350mW
Q2 Q3 Q5 Q6 Q8 Q9 = 2N2222A: Transistor NPN; Mfg: Fairchild; Part Number: MMBT2222A; Rating: 350mW
R10 R27 = RESISTOR: Resistor; Mfg: Panasonic; Part Number: ERJ-2GEJ103X; Rating: 1/10W; Tolerance: 5%
R11 R20 R28 = RESISTOR: Resistor; Mfg: Panasonic; Part Number: ERJ-3GEYJ120V; Rating: 1/10W; Tolerance: 5%
R12 R19 R21 = RESISTOR: Resistor; Mfg: Panasonic; Part Number: ERJ-2GEJ332X; Rating: 1/10W; tolerance: 5%
R13 R14 R30 = RESISTOR: Resistor; Mfg: Panasonic; Part Number: ERJ-2GEJ102X; Rating: 1/10W; Tolerance: 5%
R15 = RESISTOR_dsize: Resistor; Mfg: Panasonic; Part Number: ERJ-3EKF3603V; Rating: 1/10W; Tolerance: 1%
R17 = RES: Resistor; ICA_MFR_NAME: YAGEO; ICA_PARTNUM: $$2140285$$RC0603FR-0715KL; Mfg: Yageo; Part Number: RC0603FR-0715KL; Rating: 1/10W; Tolerance: 1%
R18 R25 = RESISTOR_dsize: Resistor; Mfg: Panasonic; Part Number: ERJ-3EKF5602V; Rating: 1/10W; Tolerance: 1%
R22 = R: Resistor; ICA_MFR_NAME: PANASONIC; ICA_PARTNUM: $$1784362$$ERJ-3GEYJ753; Mfg: Panasonic; Part Number: ERJ-3EKF7502V; Rating: 1/10W; Tolerance: 1%
R23 = RESISTOR_dsize: Resistor; Mfg: Panasonic; Part Number: ERJ-3GEYJ624V; Rating: 1/10W; Tolerance: 1%
R24 = RESISTOR_dsize: Resistor; Mfg: Panasonic; Part Number: ERJ-3EKF6803V; Rating: 1/10W; Tolerance: 1%
R26 = RESISTOR_dsize: Resistor; CCA ITEM: 110; ICA_MFR_NAME: PANASONIC; ICA_PARTNUM: $$1785380$$ERJ-3GSYJ330V; Mfg: Panasonic; Part Number: ERJ-3GEY0R00V; RATING/TOLERANCE: <RATING/TOLERANCE>; Rating: 1/10W
R29 = RESISTOR: Resistor; Mfg: Panasonic; Part Number: ERJ-2GEJ222X; Rating: 1/10W; Tolerance: 5%
TP3 TP4 TP6 TP14-TP41 = Testpoint: Part Number: TMP-543
TP5 TP7 = Testpoint: Part Number: NEW-TMP-543
U1 = TPS65145_11: IC Voltage Regulator; Mfg: TI; Part Number: TPS65145PWP
R31 = R: Resistor; CCA ITEM: 13; MFG: Yageo; Part Number: RC0603FR-0733RL; Rating: 1/10W; Tolerance: 1%
U2 = p9_WQXGA_TypeA_DMD_0
C26-C37 C39-C41 C43-C52 C54-C63 C65-C74 C76-C90 = CAP_NP_dsize: Capacitor; ESR: <ESR>; ICA_MFR_NAME: PANASONIC; ICA_PARTNUM: $$2075017$$ECJ1VB1E104K; Mfg: TDK; Part Number: C1608X7R1E104K; Rating: 25V; Rating/Tolerance: 25V,10%; Tolerance: 10%; Type: X7R
C42 C53 C64 C75 = CAP_NP_dsize: Capacitor; ESR: <ESR>; ICA_MFR_NAME: PANASONIC; ICA_PARTNUM: $$2075017$$ECJ1VB1E104K; Mfg: Murata; Part Number: GRM188R61A225ME34D; Rating: 10V; Rating/Tolerance: 10V,10%; Tolerance: 20%; Type: X5R
R32 R33 = RESISTOR_dsize: Resistor; Do Not Install: Do Not Install; ICA_MFR_NAME: YAGEO; ICA_PARTNUM: $$482834$$RC0603JRF070R0; Mfg: Panasonic; Part Number: ERJ-3GEY0R00V; Rating: 1/10W

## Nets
GND: C1.2 C2.2 C3.2 C4.2 C5.2 C6.2 C7.2 C8.2 C9.2 C11.1 C13.2 C14.2 C15.1 C18.2 C20.2 C21.1 C22.2 C23.2 C24.1 C25.2 C26.2 C27.2 C28.2 C29.2 C30.2 C31.2 C32.2 C33.2 C34.2 C35.2 C36.2 C37.2 C38.1 C39.2 C40.2 C41.2 C42.2 C43.2 C44.2 C45.2 C46.2 C47.2 C48.2 C49.2 C50.2 C51.2 C52.2 C53.2 C54.2 C55.2 C56.2 C57.2 C58.2 C59.2 C60.2 C61.2 C62.2 C63.2 C64.2 C65.2 C66.2 C67.2 C68.2 C69.2 C70.2 C71.2 C72.2 C73.2 C74.2 C75.2 C76.2 C77.2 C78.2 C79.2 C80.2 C81.2 C82.2 C83.2 C84.2 C85.2 C86.2 C87.2 C88.2 C89.2 C90.2 D1.2(ANODE) D3.2(ANODE) D4.2(K2) J1.1A J1.1D J1.2C J1.2F J1.3A J1.3D J1.4C J1.4F J1.5A J1.5D J1.6C J1.6F J1.7A J1.7D J1.8C J1.8F J1.9A J1.9D J1.10C J1.10F J1.11A J1.11D J1.12C J1.12F J1.13D J1.14C J1.14F J1.15A J1.15D J1.16C J1.16F J1.17A J1.17D J1.18C J1.18F J1.19A J1.19D J1.20C J1.20F J1.21A J1.21D J1.22C J1.22F J1.23A J1.23D J1.24C J1.24F J1.25A J1.25D J1MT1.1 J1MT2.1 J2.1A J2.1D J2.2C J2.2F J2.3A J2.3D J2.4C J2.4F J2.5A J2.5D J2.6C J2.6F J2.7A J2.7D J2.8C J2.8F J2.9A J2.9D J2.10C J2.10F J2.11A J2.11D J2.12C J2.12F J2.13D J2.14C J2.14F J2.15A J2.15D J2.16C J2.16F J2.17A J2.17D J2.18C J2.18F J2.19A J2.19D J2.20C J2.20F J2.21A J2.21D J2.22C J2.22F J2.23A J2.23D J2.24C J2.24F J2.25A J2.25D J2MT1.1 J2MT2.1 Q2.1(EMITTER) Q3.1(EMITTER) Q4.2(BASE) Q5.3(COLLECTOR) Q7.3(COLLECTOR) Q8.1(EMITTER) Q9.1(EMITTER) R16.1 R18.2 R19.1 R25.1 TP2.1 TP8.1 TP9.1 TP10.1 TP11.1 U1.7(PGND) U1.8(PGND) U1.11(GND) U1.19(GND) U1.23(ENR) U1.25(POWER_PAD) U2.A1(VSS(GND)) U2.AB2(VSS(GND)) U2.AB4(VSS(GND)) U2.AB6(VSS(GND)) U2.AB26(VSS(GND)) U2.AB28(VSS(GND)) U2.AB30(VSS(GND)) U2.AC5(VSS(GND)) U2.AD30(VSS(GND)) U2.AE7(VSS(GND)) U2.AE13(VSS(GND)) U2.AE19(VSS(GND)) U2.AE25(VSS(GND)) U2.AF6(VSS(GND)) U2.AF12(VSS(GND)) U2.AF18(VSS(GND)) U2.AF24(VSS(GND)) U2.AF30(VSS(GND)) U2.AG7(VSS(GND)) U2.AG13(VSS(GND)) U2.AG19(VSS(GND)) U2.AG25(VSS(GND)) U2.AH6(VSS(GND)) U2.AH12(VSS(GND)) U2.AH18(VSS(GND)) U2.AH24(VSS(GND)) U2.AH30(VSS(GND)) U2.AJ1(VSS(GND)) U2.AJ7(VSS(GND)) U2.AJ13(VSS(GND)) U2.AJ19(VSS(GND)) U2.AJ25(VSS(GND)) U2.AK6(VSS(GND)) U2.AK12(VSS(GND)) U2.AK18(VSS(GND)) U2.AL29(VSS(GND)) U2.B12(VSS(GND)) U2.B18(VSS(GND)) U2.B24(VSS(GND)) U2.B30(VSS(GND)) U2.C7(VSS(GND)) U2.C13(VSS(GND)) U2.C19(VSS(GND)) U2.C25(VSS(GND)) U2.D6(VSS(GND)) U2.D12(VSS(GND)) U2.D18(VSS(GND)) U2.D24(VSS(GND)) U2.D30(VSS(GND)) U2.E1(VSS(GND)) U2.E7(VSS(GND)) U2.E13(VSS(GND)) U2.E19(VSS(GND)) U2.E25(VSS(GND)) U2.F6(VSS(GND)) U2.F12(VSS(GND)) U2.F18(VSS(GND)) U2.F24(VSS(GND)) U2.F30(VSS(GND)) U2.G7(VSS(GND)) U2.G13(VSS(GND)) U2.G19(VSS(GND)) U2.G25(VSS(GND)) U2.K4(VSS(GND)) U2.K6(VSS(GND)) U2.K26(VSS(GND)) U2.K28(VSS(GND)) U2.K30(VSS(GND)) U2.M2(VSS(GND)) U2.M30(VSS(GND)) U2.N5(VSS(GND)) U2.N27(VSS(GND)) U2.R5(VSS(GND)) U2.T2(VSS(GND)) U2.T30(VSS(GND)) U2.U27(VSS(GND)) U2.V2(VSS(GND)) U2.V30(VSS(GND)) U2.W5(VSS(GND)) U2.Y28(VSS(GND))
C1+: C16.1 U1.16(C1+)
C1-: C16.2 U1.17(C1-)
C2+: C19.1 U1.14(C2+)
C2-: C19.2 U1.15(C2-/MODE)
COMP: R17.2 U1.22(COMP)
DAD_ADDR_0: J1.13E R6.1
DAD_ADDR_1: J1.13C R7.2
DAD_ADDR_2: J1.12E R5.1
DAD_ADDR_3: J1.12D R4.1
DAD_OEZ: J1.14A R1.1 R8.2
DADADDR_0: R6.2 U2.H12(A0)
DADADDR_1: R7.1 U2.C5(A1)
DADADDR_2: R5.2 U2.B6(A2)
DADADDR_3: R4.2 U2.A19(A3)
DADIRQZ: J1.11C U2.C3(IRQZ)
DADMODE_0: J1.11F U2.J1(MODE0)
DADMODE_1: J1.11E U2.G1(MODE1)
DADOEZ: C5.1 R8.1 U2.AK24(OEZ)
DADSEL_0: J1.12B U2.AK4(SEL0)
DADSEL_1: J1.12A U2.AL13(SEL1)
DADSTRB: J1.13F U2.H6(STROBE)
DCLK_AN: J2.21E U2.H2(DCLK_AN)
DCLK_AP: J2.21F U2.H4(DCLK_AP)
DCLK_BN: J2.5E U2.AJ5(DCLK_BN)
DCLK_BP: J2.5F U2.AJ3(DCLK_BP)
DCLK_CN: J1.5E U2.C23(DCLK_CN)
DCLK_CP: J1.5F U2.C21(DCLK_CP)
DCLK_DN: J1.21E U2.AH22(DCLK_DN)
DCLK_DP: J1.21F U2.AH20(DCLK_DP)
DD_AN0: J2.16A U2.H10(D_AN_0)
DD_AN1: J2.17E U2.G3(D_AN_1)
DD_AN2: J2.17B U2.G9(D_AN_2)
DD_AN3: J2.18D U2.F4(D_AN_3)
DD_AN4: J2.18A U2.F10(D_AN_4)
DD_AN5: J2.19E U2.E3(D_AN_5)
DD_AN6: J2.19B U2.E9(D_AN_6)
DD_AN7: J2.20D U2.D2(D_AN_7)
DD_AN8: J2.21B U2.J5(D_AN_8)
DD_AN9: J2.22D U2.C9(D_AN_9)
DD_AN10: J2.22A U2.F14(D_AN_10)
DD_AN11: J2.23E U2.B8(D_AN_11)
DD_AN12: J2.23B U2.G15(D_AN_12)
DD_AN13: J2.24D U2.B14(D_AN_13)
DD_AN14: J2.24A U2.H16(D_AN_14)
DD_AN15: J2.25B U2.D16(D_AN_15)
DD_AP0: J2.16B U2.H8(D_AP_0)
DD_AP1: J2.17F U2.G5(D_AP_1)
DD_AP2: J2.17C U2.G11(D_AP_2)
DD_AP3: J2.18E U2.F2(D_AP_3)
DD_AP4: J2.18B U2.F8(D_AP_4)
DD_AP5: J2.19F U2.E5(D_AP_5)
DD_AP6: J2.19C U2.E11(D_AP_6)
DD_AP7: J2.20E U2.D4(D_AP_7)
DD_AP8: J2.21C U2.J3(D_AP_8)
DD_AP9: J2.22E U2.C11(D_AP_9)
DD_AP10: J2.22B U2.F16(D_AP_10)
DD_AP11: J2.23F U2.B10(D_AP_11)
DD_AP12: J2.23C U2.H14(D_AP_12)
DD_AP13: J2.24E U2.B16(D_AP_13)
DD_AP14: J2.24B U2.G17(D_AP_14)
DD_AP15: J2.25C U2.D14(D_AP_15)
DD_BN0: J2.10A U2.AD8(D_BN_0)
DD_BN1: J2.9E U2.AE3(D_BN_1)
DD_BN2: J2.9B U2.AF8(D_BN_2)
DD_BN3: J2.8D U2.AF2(D_BN_3)
DD_BN4: J2.8A U2.AG5(D_BN_4)
DD_BN5: J2.7E U2.AH8(D_BN_5)
DD_BN6: J2.7B U2.AG9(D_BN_6)
DD_BN7: J2.6D U2.AH2(D_BN_7)
DD_BN8: J2.5B U2.AL9(D_BN_8)
DD_BN9: J2.4D U2.AJ11(D_BN_9)
DD_BN10: J2.4A U2.AF14(D_BN_10)
DD_BN11: J2.3E U2.AE11(D_BN_11)
DD_BN12: J2.3B U2.AH16(D_BN_12)
DD_BN13: J2.2D U2.AD14(D_BN_13)
DD_BN14: J2.2A U2.AG17(D_BN_14)
DD_BN15: J2.1E U2.AD16(D_BN_15)
DD_BP0: J2.10B U2.AD10(D_BP_0)
DD_BP1: J2.9F U2.AE5(D_BP_1)
DD_BP2: J2.9C U2.AF10(D_BP_2)
DD_BP3: J2.8E U2.AF4(D_BP_3)
DD_BP4: J2.8B U2.AG3(D_BP_4)
DD_BP5: J2.7F U2.AH10(D_BP_5)
DD_BP6: J2.7C U2.AG11(D_BP_6)
DD_BP7: J2.6E U2.AH4(D_BP_7)
DD_BP8: J2.5C U2.AL11(D_BP_8)
DD_BP9: J2.4E U2.AJ9(D_BP_9)
DD_BP10: J2.4B U2.AF16(D_BP_10)
DD_BP11: J2.3F U2.AE9(D_BP_11)
DD_BP12: J2.3C U2.AH14(D_BP_12)
DD_BP13: J2.2E U2.AE15(D_BP_13)
DD_BP14: J2.2B U2.AG15(D_BP_14)
DD_BP15: J2.1F U2.AE17(D_BP_15)
DD_CN0: J1.1E U2.C15(D_CN_0)
DD_CN1: J1.2A U2.E15(D_CN_1)
DD_CN2: J1.2D U2.A17(D_CN_2)
DD_CN3: J1.3B U2.F20(D_CN_3)
DD_CN4: J1.3E U2.B20(D_CN_4)
DD_CN5: J1.4A U2.G21(D_CN_5)
DD_CN6: J1.4D U2.D22(D_CN_6)
DD_CN7: J1.5B U2.E23(D_CN_7)
DD_CN8: J1.6D U2.B26(D_CN_8)
DD_CN9: J1.7B U2.F28(D_CN_9)
DD_CN10: J1.7E U2.C27(D_CN_10)
DD_CN11: J1.8A U2.J29(D_CN_11)
DD_CN12: J1.8D U2.D26(D_CN_12)
DD_CN13: J1.9B U2.H26(D_CN_13)
DD_CN14: J1.9E U2.E29(D_CN_14)
DD_CN15: J1.10A U2.G29(D_CN_15)
DD_CP0: J1.1F U2.C17(D_CP_0)
DD_CP1: J1.2B U2.E17(D_CP_1)
DD_CP2: J1.2E U2.A15(D_CP_2)
DD_CP3: J1.3C U2.F22(D_CP_3)
DD_CP4: J1.3F U2.B22(D_CP_4)
DD_CP5: J1.4B U2.H20(D_CP_5)
DD_CP6: J1.4E U2.D20(D_CP_6)
DD_CP7: J1.5C U2.E21(D_CP_7)
DD_CP8: J1.6E U2.B28(D_CP_8)
DD_CP9: J1.7C U2.F26(D_CP_9)
DD_CP10: J1.7F U2.C29(D_CP_10)
DD_CP11: J1.8B U2.J27(D_CP_11)
DD_CP12: J1.8E U2.D28(D_CP_12)
DD_CP13: J1.9C U2.H28(D_CP_13)
DD_CP14: J1.9F U2.E27(D_CP_14)
DD_CP15: J1.10B U2.G27(D_CP_15)
DD_DN0: J1.25B U2.AJ15(D_DN_0)
DD_DN1: J1.24A U2.AC27(D_DN_1)
DD_DN2: J1.24D U2.AK16(D_DN_2)
DD_DN3: J1.23B U2.AE29(D_DN_3)
DD_DN4: J1.23E U2.AE21(D_DN_4)
DD_DN5: J1.22A U2.AF20(D_DN_5)
DD_DN6: J1.22D U2.AL15(D_DN_6)
DD_DN7: J1.21B U2.AG29(D_DN_7)
DD_DN8: J1.20D U2.AD22(D_DN_8)
DD_DN9: J1.19B U2.AG21(D_DN_9)
DD_DN10: J1.19E U2.AJ23(D_DN_10)
DD_DN11: J1.18A U2.AJ29(D_DN_11)
DD_DN12: J1.18D U2.AF28(D_DN_12)
DD_DN13: J1.17B U2.AK22(D_DN_13)
DD_DN14: J1.17E U2.AD28(D_DN_14)
DD_DN15: J1.16A U2.AK28(D_DN_15)
DD_DP0: J1.25C U2.AJ17(D_DP_0)
DD_DP1: J1.24B U2.AC29(D_DP_1)
DD_DP2: J1.24E U2.AK14(D_DP_2)
DD_DP3: J1.23C U2.AE27(D_DP_3)
DD_DP4: J1.23F U2.AD20(D_DP_4)
DD_DP5: J1.22B U2.AF22(D_DP_5)
DD_DP6: J1.22E U2.AL17(D_DP_6)
DD_DP7: J1.21C U2.AG27(D_DP_7)
DD_DP8: J1.20E U2.AE23(D_DP_8)
DD_DP9: J1.19C U2.AG23(D_DP_9)
DD_DP10: J1.19F U2.AJ21(D_DP_10)
DD_DP11: J1.18B U2.AJ27(D_DP_11)
DD_DP12: J1.18E U2.AF26(D_DP_12)
DD_DP13: J1.17C U2.AK20(D_DP_13)
DD_DP14: J1.17F U2.AD26(D_DP_14)
DD_DP15: J1.16B U2.AK26(D_DP_15)
DMD_P3P3V: C1.1 C2.1 C7.1 C9.1 C11.2 C29.1 C30.1 C31.1 C32.1 C33.1 C34.1 C38.2 C39.1 C40.1 C41.1 C42.1 C43.1 C44.1 C45.1 C46.1 C47.1 C48.1 C49.1 C50.1 C51.1 C52.1 C53.1 C54.1 C55.1 C56.1 C57.1 C58.1 C59.1 C60.1 C61.1 C62.1 C63.1 C64.1 C65.1 C66.1 C67.1 C68.1 C69.1 C70.1 C71.1 C72.1 C73.1 C74.1 C75.1 C76.1 C77.1 J3.1 L1.2 L2.2 L3.1 L4.1 L5.1 R1.2 R2.2 R3.2 R12.1 R29.1 TP1.1 U1.4(Vin) U2.A21(VCC) U2.A23(VCC) U2.A25(VCC) U2.A27(VCC) U2.A29(VCC) U2.AC31(VCC) U2.AD6(VCCI) U2.AD12(VCCI) U2.AD18(VCCI) U2.AD24(VCCI) U2.AE31(VCC) U2.AG1(VCC) U2.AG31(VCC) U2.AJ31(VCC) U2.AK2(VCC) U2.AK30(VCC) U2.AL3(VCC) U2.AL5(VCC) U2.AL7(VCC) U2.AL21(VCC) U2.AL23(VCC) U2.AL25(VCC) U2.AL27(VCC) U2.C1(VCC) U2.C31(VCC) U2.E31(VCC) U2.G31(VCC) U2.H18(VCCI) U2.H24(VCCI) U2.J31(VCC) U2.K2(VCC) U2.M6(VCCI) U2.M26(VCCI) U2.P6(VCCI) U2.P26(VCCI) U2.T6(VCCI) U2.T26(VCCI) U2.V6(VCCI) U2.V26(VCCI) U2.Y6(VCCI) U2.Y26(VCCI)
DMD_RSTZ: R9.1 U2.AL19(RESETZ) U2.B4(PWRDNZ)
DMDRSTZ: J1.15B R2.1 R9.2
DRV: C17.2 U1.18(DRV)
DRV_1: C17.1 D4.3(K1)
DRV_D: C10.1 D5.3(K1)
EN_BIAS: R32.1 U2.J15(EN_BIAS)
EN_OFFSET: J3.2 R13.1 R14.1 R16.2 R30.1 TP3.1 U1.24(EN) U2.H30(EN_OFFSET)
EN_RESET: R33.1 U2.J17(EN_RESET)
FB1: C12.2 R15.2 R18.1 U1.1(FB1)
FB2: R22.2 R23.1 U1.21(FB2)
FB3: R24.2 R25.2 U1.12(FB3)
MBRST0: TP12.1 U2.L5(MBRST_0)
MBRST1: TP31.1 U2.M28(MBRST_1)
MBRST2: TP15.1 U2.P4(MBRST_2)
MBRST3: TP17.1 U2.P30(MBRST_3)
MBRST4: TP19.1 U2.L3(MBRST_4)
MBRST5: TP32.1 U2.P28(MBRST_5)
MBRST6: TP22.1 U2.P2(MBRST_6)
MBRST7: TP24.1 U2.T28(MBRST_7)
MBRST8: TP26.1 U2.M4(MBRST_8)
MBRST9: TP27.1 U2.L29(MBRST_9)
MBRST10: TP28.1 U2.T4(MBRST_10)
MBRST11: TP29.1 U2.N29(MBRST_11)
MBRST12: TP30.1 U2.N3(MBRST_12)
MBRST13: TP38.1 U2.L27(MBRST_13)
MBRST14: TP40.1 U2.R3(MBRST_14)
MBRST15: TP42.1 U2.V28(MBRST_15)
MBRST16: TP13.1 U2.V4(MBRST_16)
MBRST17: TP14.1 U2.R29(MBRST_17)
MBRST18: TP16.1 U2.Y4(MBRST_18)
MBRST19: TP18.1 U2.AA27(MBRST_19)
MBRST20: TP20.1 U2.W3(MBRST_20)
MBRST21: TP21.1 U2.W27(MBRST_21)
MBRST22: TP23.1 U2.AA3(MBRST_22)
MBRST23: TP25.1 U2.W29(MBRST_23)
MBRST24: TP33.1 U2.U5(MBRST_24)
MBRST25: TP34.1 U2.U29(MBRST_25)
MBRST26: TP35.1 U2.Y2(MBRST_26)
MBRST27: TP36.1 U2.AA29(MBRST_27)
MBRST28: TP37.1 U2.U3(MBRST_28)
MBRST29: TP39.1 U2.Y30(MBRST_29)
MBRST30: TP41.1 U2.AA5(MBRST_30)
MBRST31: TP43.1 U2.R27(MBRST_31)
P3P3V1: C3.1 J1.1B J1.1C L1.1
P3P3V2: C4.1 J2.1B J2.1C L2.1
P3P3V3: C6.1 J1.25E J1.25F L3.2
P3P3V4: C8.1 J2.25E J2.25F L4.2
PG: R26.1 U1.10(PG)
PG_BIAS: R32.2 U2.J19(PG_BIAS)
PG_OFFSET: R26.2 TP7.1 U2.A13(PG_OFFSET)
PG_RESET: R33.2 U2.AC19(PG_RESET)
REF: C23.1 R22.1 U1.20(REF)
SCP_CLK: J1.16D U2.AE1(SCPCLK)
SCP_DI: J1.15C R31.1
SCP_DMD_CSZ: J1.15E R3.1 U2.AD4(SCPENZ)
SCP_DO: J1.16E U2.AD2(SCPDI)
SCPDO_DMD2ASIC: R31.2 U2.AC3(SCPDO)
SCTRL_AN: J2.20A U2.D8(SCTRL_AN)
SCTRL_AP: J2.20B U2.D10(SCTRL_AP)
SCTRL_BN: J2.6A U2.AK8(SCTRL_BN)
SCTRL_BP: J2.6B U2.AK10(SCTRL_BP)
SCTRL_CN: J1.6A U2.G23(SCTRL_CN)
SCTRL_CP: J1.6B U2.H22(SCTRL_CP)
SCTRL_DN: J1.20A U2.AH28(SCTRL_DN)
SCTRL_DP: J1.20B U2.AH26(SCTRL_DP)
SW0_1: C10.2 D2.1(ANODE) L5.2 U1.5(SW0) U1.6(SW1)
VBIAS: C24.2 C25.1 C85.1 C86.1 C87.1 C88.1 C89.1 C90.1 R24.1 R27.1 R28.1 TP6.1 U1.13(OUT3) U2.A3(VBIAS) U2.A5(VBIAS) U2.A7(VBIAS) U2.A9(VBIAS) U2.A11(VBIAS) U2.B2(VBIAS)
VOFFSET: C12.1 C13.1 C14.1 C78.1 C79.1 C80.1 C81.1 C82.1 C83.1 C84.1 D2.2(CATHODE) D3.1(CATHODE) R10.1 R11.1 R15.1 TP4.1 U1.9(SUP_OUT1) U2.AA1(VOFFSET) U2.AC1(VOFFSET) U2.L1(VOFFSET) U2.N1(VOFFSET) U2.R1(VOFFSET) U2.U1(VOFFSET) U2.W1(VOFFSET)
VRESET: C20.1 C21.2 C22.1 C26.1 C27.1 C28.1 C35.1 C36.1 C37.1 D5.1(A1) Q6.1(EMITTER) R20.2 R21.2 R23.2 TP5.1 U2.AA31(VRESET) U2.L31(VRESET) U2.N31(VRESET) U2.R31(VRESET) U2.U31(VRESET) U2.W31(VRESET)
N25259304: Q2.2(BASE) Q3.3(COLLECTOR) R12.2
N25259348: Q9.2(BASE) R30.2
N25259473: Q4.1(EMITTER) R14.2
N25259500: Q1.2(BASE) Q2.3(COLLECTOR) R10.2
N25259508: Q4.3(COLLECTOR) Q6.2(BASE) R21.1
N25259535: Q1.1(EMITTER) R11.2
N25259593: Q5.2(BASE) Q6.3(COLLECTOR) R19.2
N25259715: Q5.1(EMITTER) R20.1
N25259725: D1.1(CATHODE) Q1.3(COLLECTOR)
N25259737: C15.2 R17.1
N25259806: C18.1 D4.1(A1) D5.2(K2)
N25259838: Q8.2(BASE) Q9.3(COLLECTOR) R29.2
N25259852: Q7.2(BASE) Q8.3(COLLECTOR) R27.2
N25259866: Q7.1(EMITTER) R28.2
N25260004: Q3.2(BASE) R13.2

Not connected (* = marked no-connect by the designer): J1 10D 10E* 11B* 13A* 13B* 14B* 14D* 14E* 15F*; J2 10D 10E 11B 11C* 11E* 11F* 12A* 12B* 12D* 12E* 13A* 13B* 13C* 13E* 13F* 14A* 14B* 14D* 14E* 15B* 15C* 15E* 15F* 16D* 16E*; U1 2(FB4)* 3(BASE)*; U2 AC7(TEST_MUX)* AC9(TP_0)* AC11(TP_1)* AC13(TP_2)* AC15(BIST_A)* AC17(TEMP)* AC21(BIST_C)* AC23(XI<2>)* AC25(XI<1>)* J7(NC1)* J9(NC2)* J11(PROG_FUSE_EN)* J13(BIST_B)* J21(BIST_D)* J23(XI<3>)* J25(NC3)*

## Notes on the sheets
sheet 1
- COMPUTER GENERATED DRAWING.  DO NOT REVISE MANUALLY
- NOTES, UNLESS OTHERWISE SPECIFIED:
- REVISIONS
- 1. The netname "DMD_P3P3V" represents connection to the +3.3V digital power plane.
- REV
- DESCRIPTION
- DATE
- APPROVED
- 2. The symbol
- represents connection to the digital ground plane.
- A
- ECO 2120805: Initial Release
- 01/04/2013
- DH
- 3. A "Z" suffix on a signal name indicates an active low signal.
- 4. All components with designators "U", "D", "Y" and "Q" are electrostatic discharge sensitive.
- 5. All resistor values are in ohms, 1/16W and 5% unless otherwise specified.
- HIGHEST REFERENCE DESIGNATORS USED
- C90
- D5
- J3
- L5
- R33
- TP43
- U2
- Q9
- 2512147
- 0314SS
- TI Information - Selective Disclosure
sheet 2
- U2
  0.9 WQXGA Type A DMD
- J1 & J2
  Input Flex
  Connector
- A/B DMD DATA (DD_AP[15:0], DD_AN[15:0], DD_BP[15:0], DD_BN[15:0])
- From
  Slave
  ASIC
- A/B DMD CLK (DCLK_AP, DCLK_AN, DCLK_BP, DCLK_BN)
- A/B SCTRL (SCTRL_AN, SCTRL_AP, SCTRL_BN, SCTRL_BP)
- C/D DMD DATA (DD_CP[15:0], DD_CN[15:0], DD_DP[15:0], DD_DN[15:0])
- C/D DMD CLK (DCLK_CP, DCLK_CN, DCLK_DP, DCLK_DN)
- From
  Master
  ASIC
- C/D SCTRL (SCTRL_CN, SCTRL_CP, SCTRL_DN, SCTRL_DP)
- DAD CONTROL (STROBE, MODE[1:0], SEL[1:0], ADDR[3:0], OEZ)
- SCP CONTROL  (CLK, DO, DI, ENZ, IRQZ)
- DMD_RSTZ
- U1
  DMD Power Supplies
- 3.3V
- VOFFSET
- VBIAS
- VRESET
- PG_OFFSET
- EN_OFFSET
- PAGE 3
- PAGE 4
- PAGE 5 & 6
- A. NG
- 1/15/2012
- TI Information - Selective Disclosure
sheet 3
- Slave LVDS
- Master LVDS
- NOTE: The C-Bus has been bit-order
  swapped (15:0 -> 0:15) from the
  standard connector pin-out
  configuration for routing purposes.
- PCB Top View
- Slave Input Connector
- Master Input Connector
- 25
- 1
- 25
- 1
- A15
- A0
- B0
- B15
- D0
- D15
- C15
- C0
- DMD
- B
- D
- A
- C
- Note: Do not install R3 if
  there is a pull-up on the
  SCP_DMD_CSZ signal on the
  Main board.
- Note: Only install one 1K Ohm
  pull-up resistor on DAD_OEZ. If
  DAD_OEZ pull-up is installed on
  Main board side, do not install
  R1.
- 12V is not used on
  pins 10D, 10E, 11B
- Pin 14B "SINGLE_ASIC_EN" is not needed
  WQXGA allows only dual ASIC
- Note: R8 and C5 are specific
  values selected to delay ASIC
  driven DAD_OEZ to allow the DMD
  enough time to park properly.
  Recommend installing values as
  shown.
- Note: 470 Ohm resistors R4 thru R9 protect the
  system when/if the wrong DMD is installed on-board.
- INPUT CONNECTOR
- A. NG
- 1/15/2012
- TI Information - Selective Disclosure
sheet 4
- Power Down Circuitry
- 3.3V
- 8.5V
- 9.1V protection diode
- -10V
- 16.0V
- DMD Power Supplies
- A. NG
- 1/15/2012
- TI Information - Selective Disclosure
sheet 5
- DMD Power/Gnd
- A. NG
- 1/15/2012
- TI Information - Selective Disclosure
sheet 6
- Bring TP for reset waveform
  MBRST 0,15,16,31 outside of
  DMD outline
- DMD Data/Control
- A. NG
- 1/15/2012
- TI Information - Selective Disclosure
